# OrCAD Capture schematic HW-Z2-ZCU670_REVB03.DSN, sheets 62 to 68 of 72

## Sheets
62 062 RFMC 2.0 Connector 2: size Custom
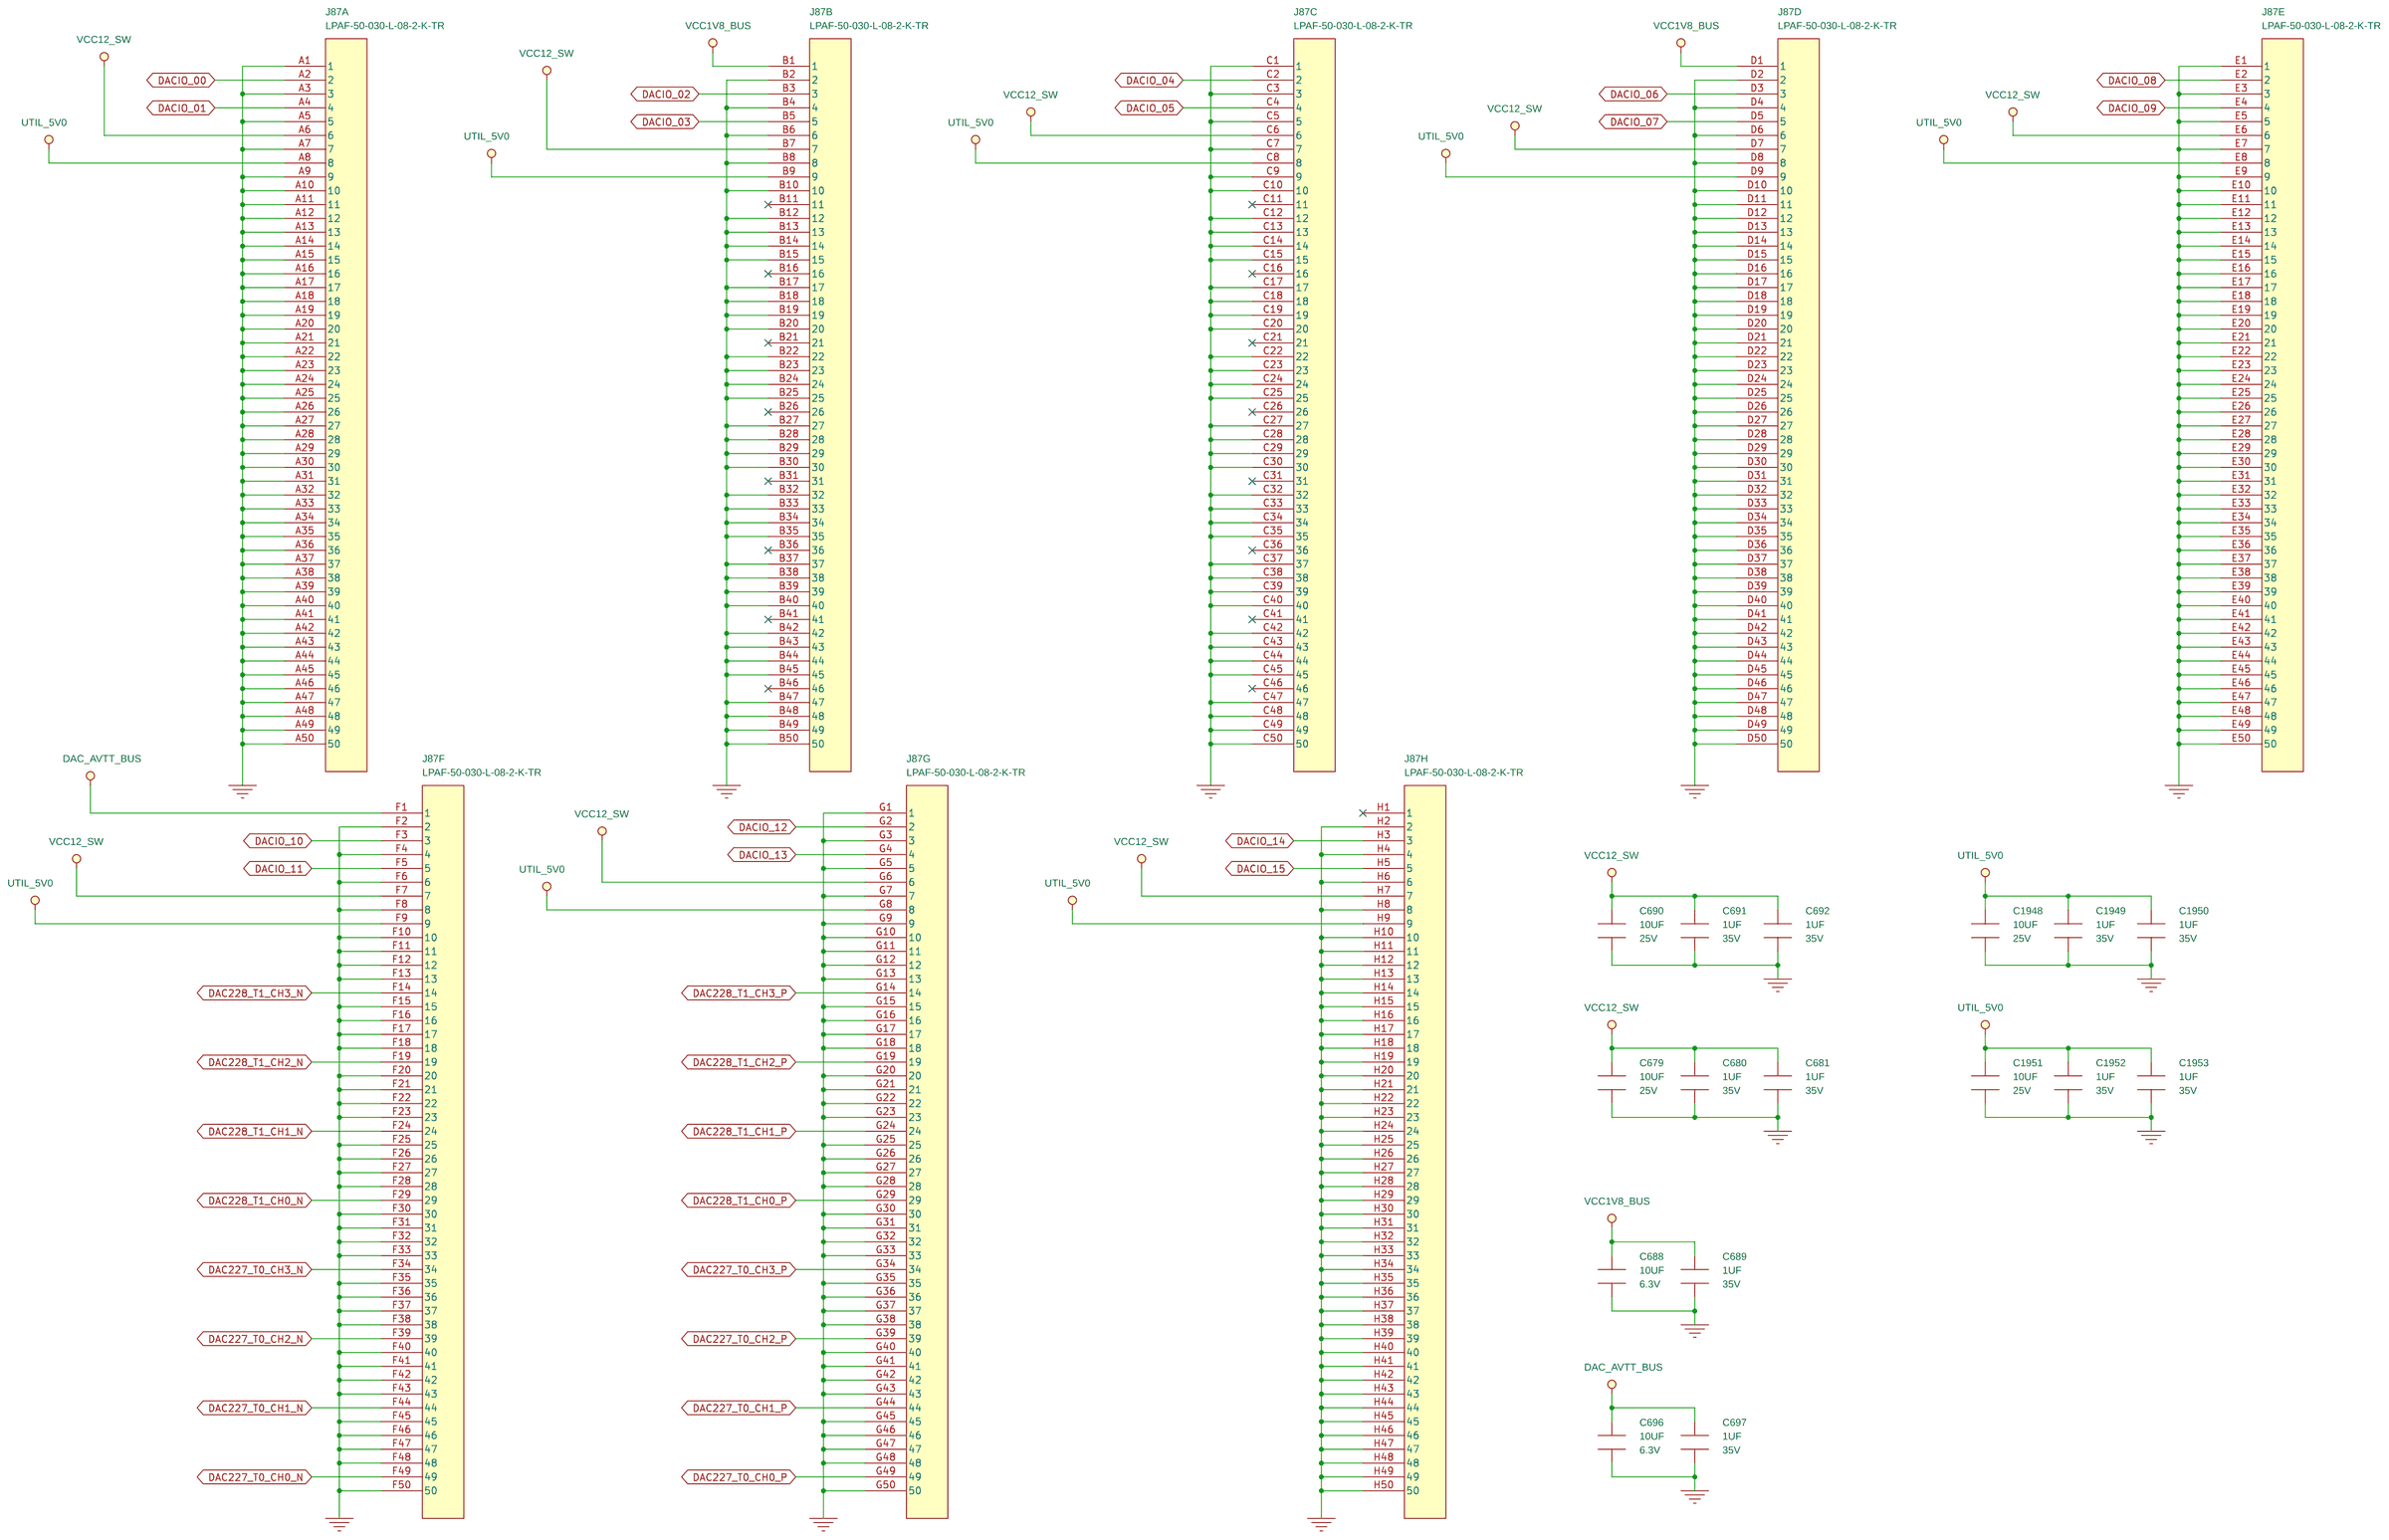
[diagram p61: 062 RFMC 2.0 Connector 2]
63 063 Mechanicals: size Custom
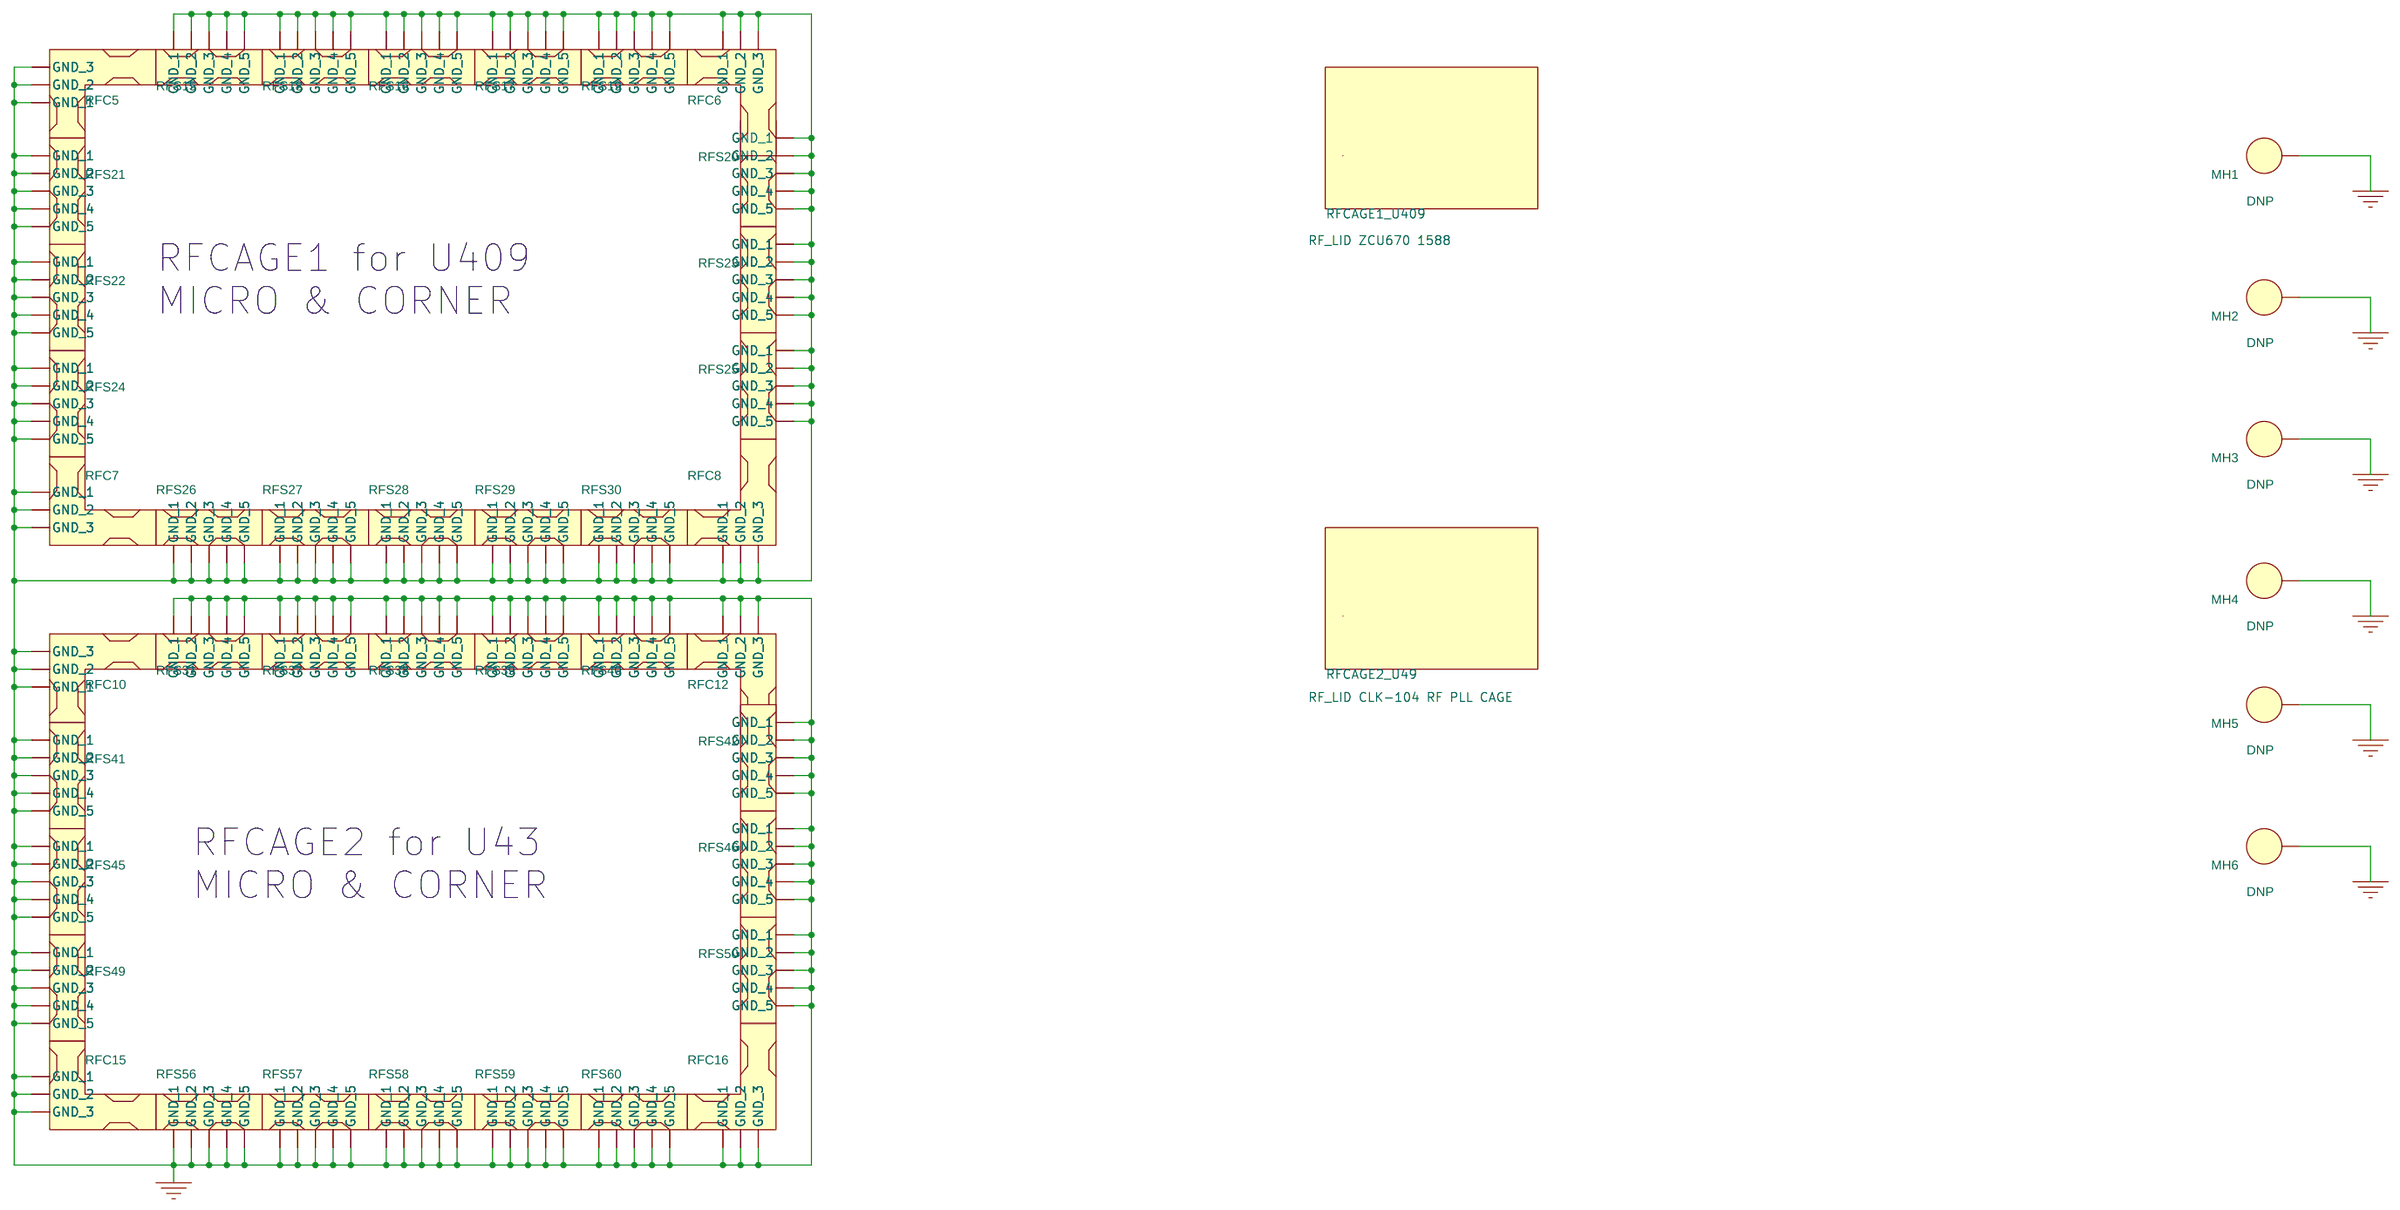
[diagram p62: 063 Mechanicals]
64 064 CLK104 Connector: size Custom
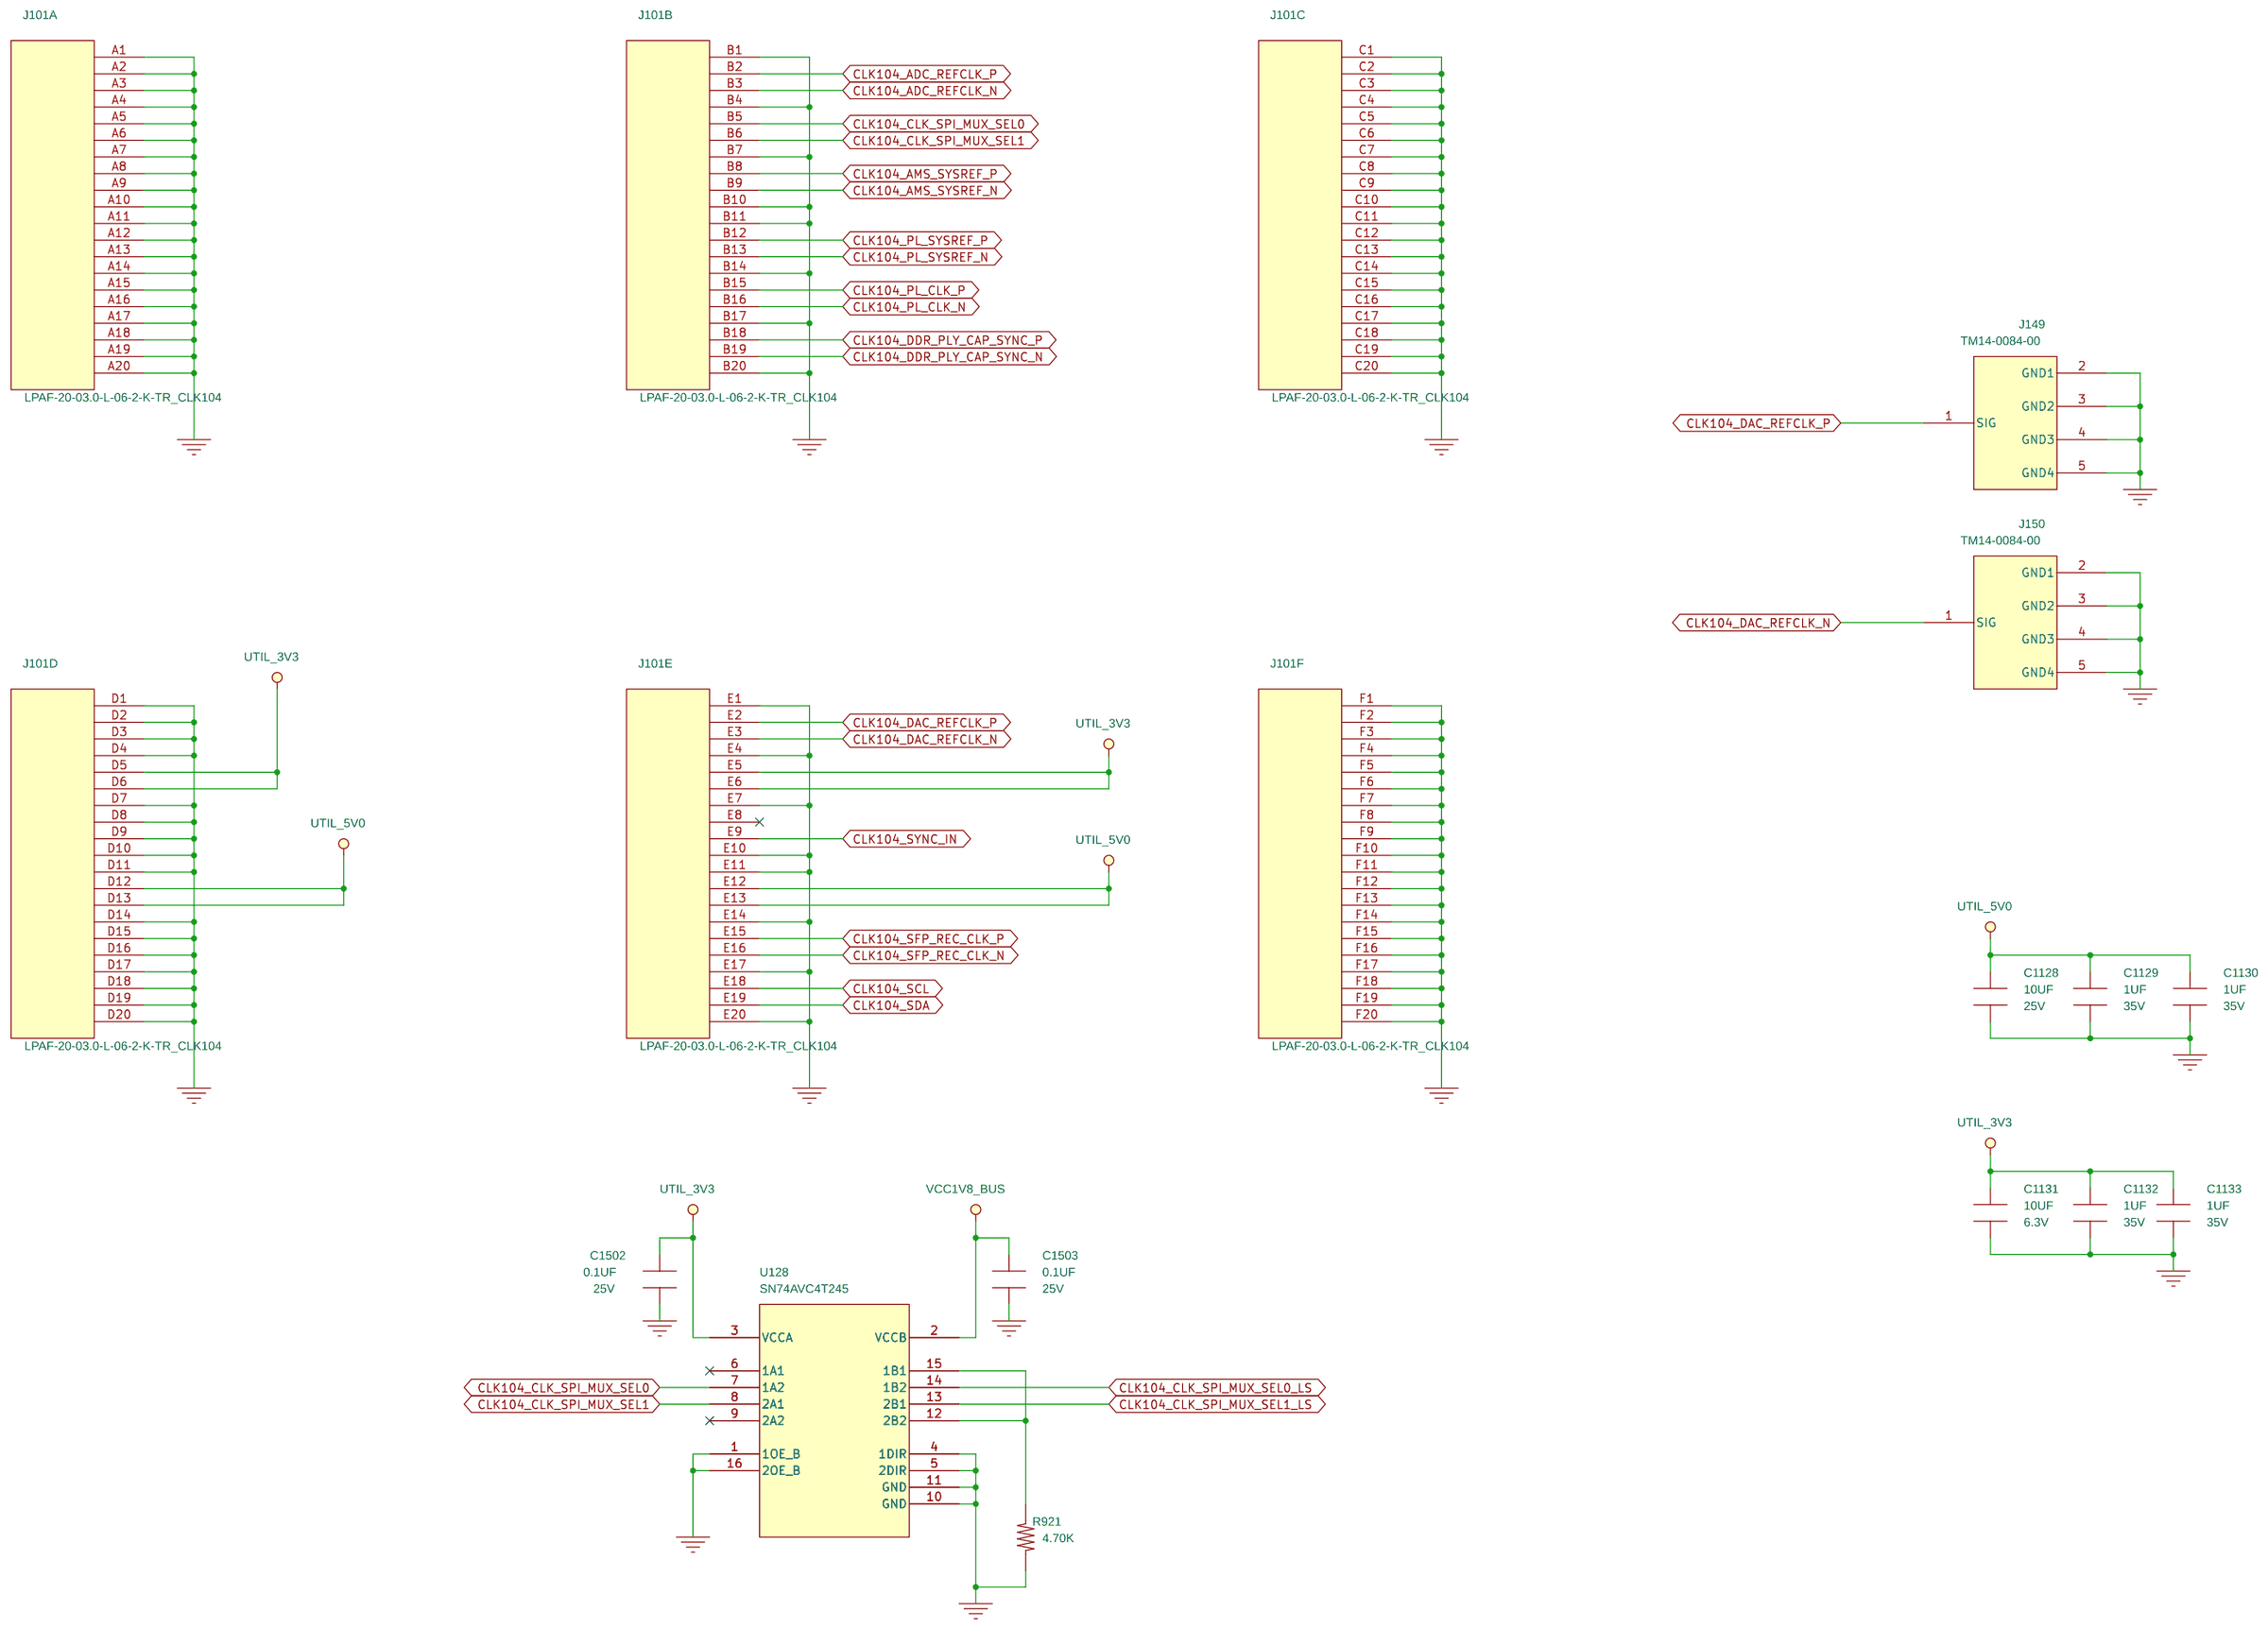
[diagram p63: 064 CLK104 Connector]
65 065 PL DDR4 C0 [7-0]: size Custom
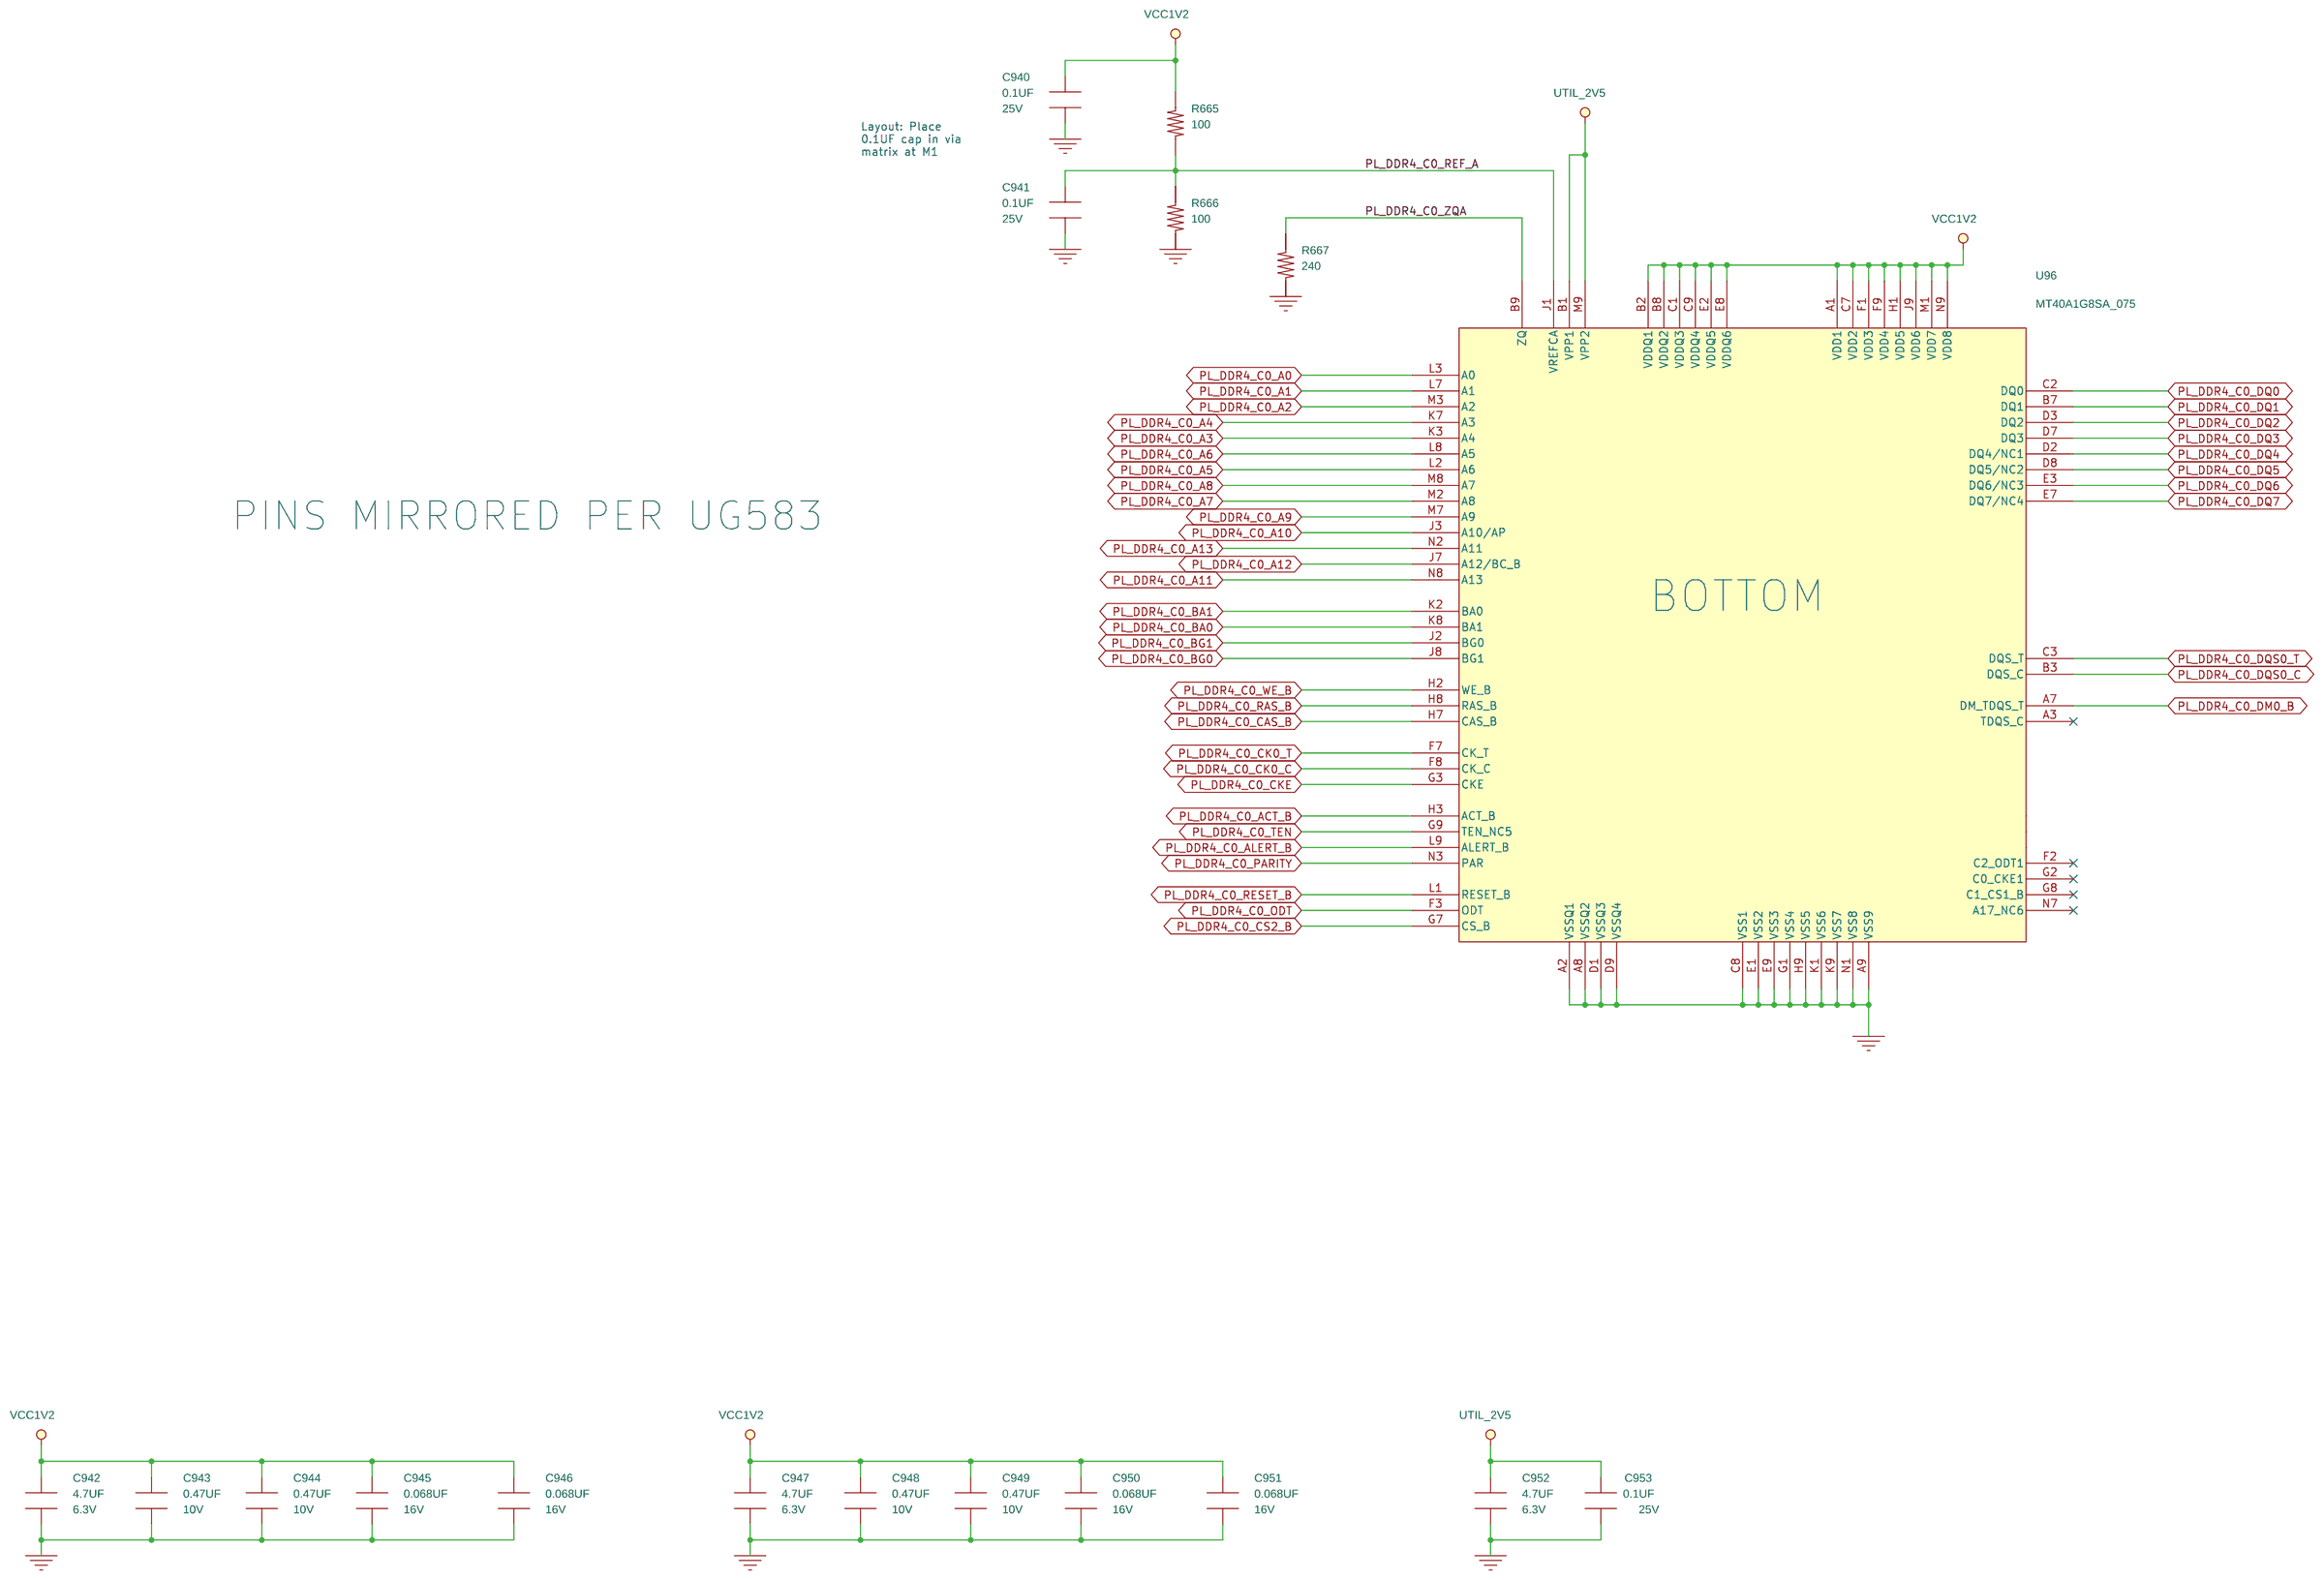
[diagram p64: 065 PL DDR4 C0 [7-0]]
66 066 PL DDR4 C0 [15-8]: size Custom
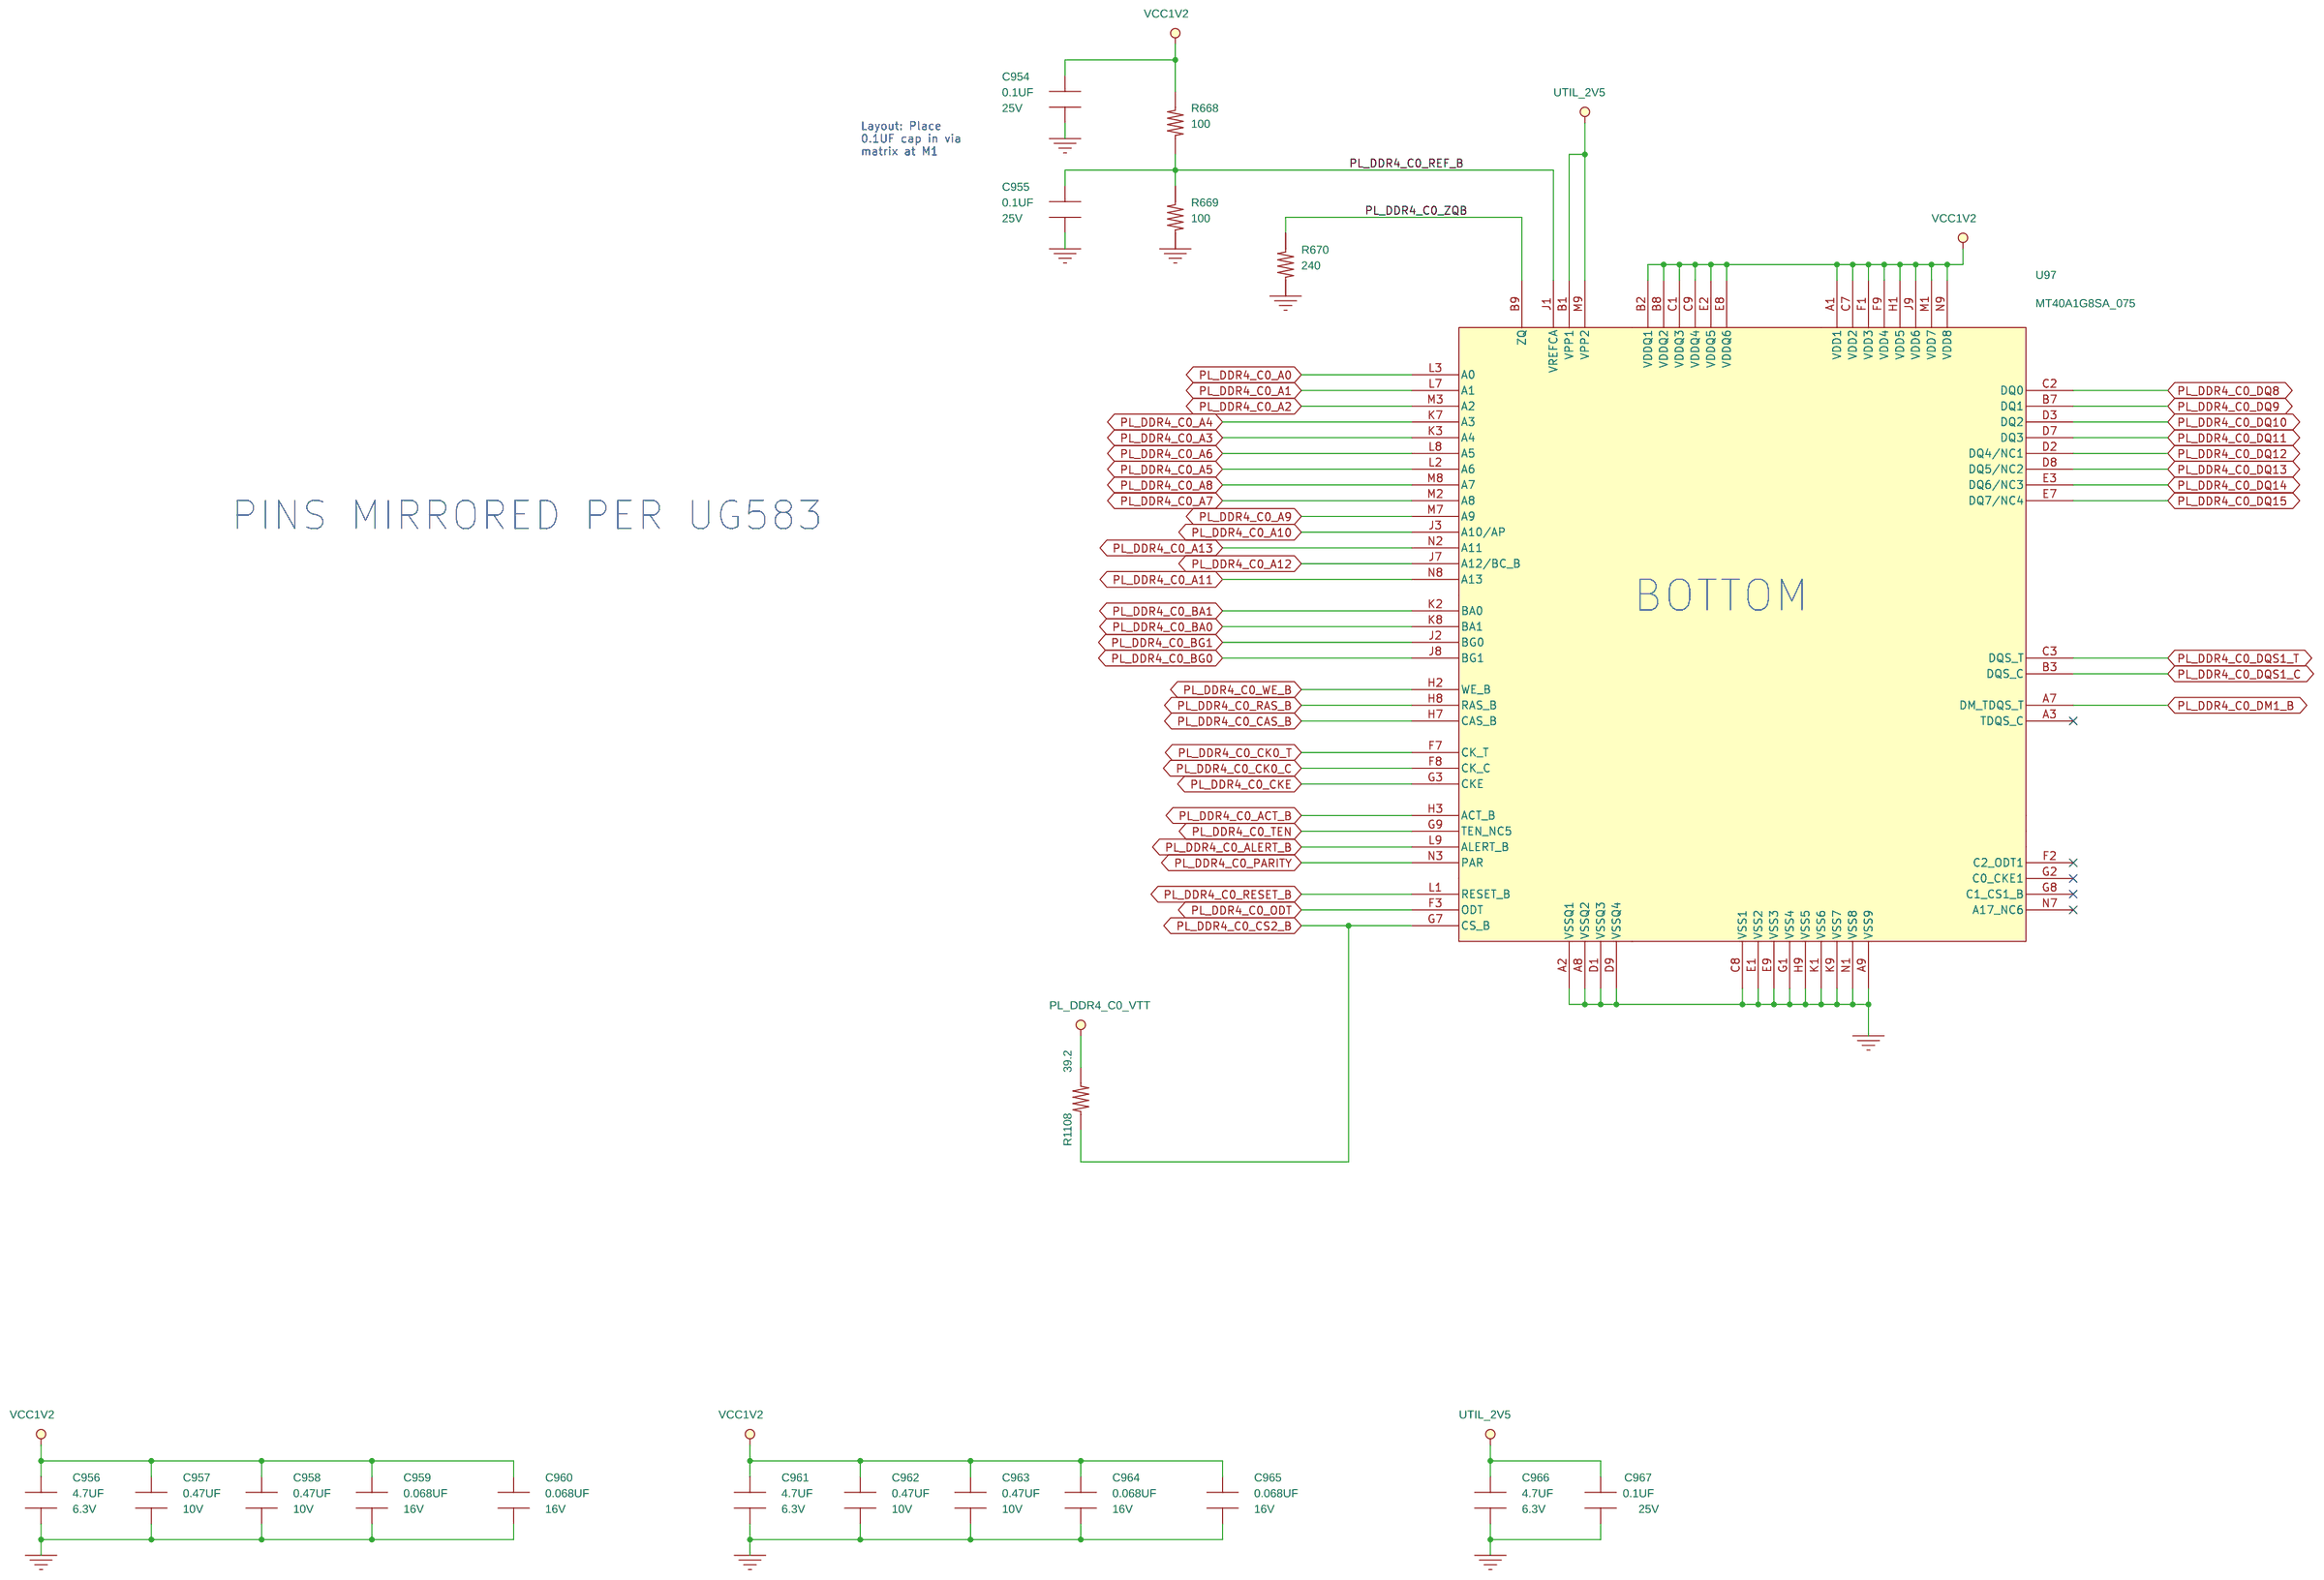
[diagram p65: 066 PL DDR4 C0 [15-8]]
67 067 PL DDR4 C0 [23-16]: size Custom
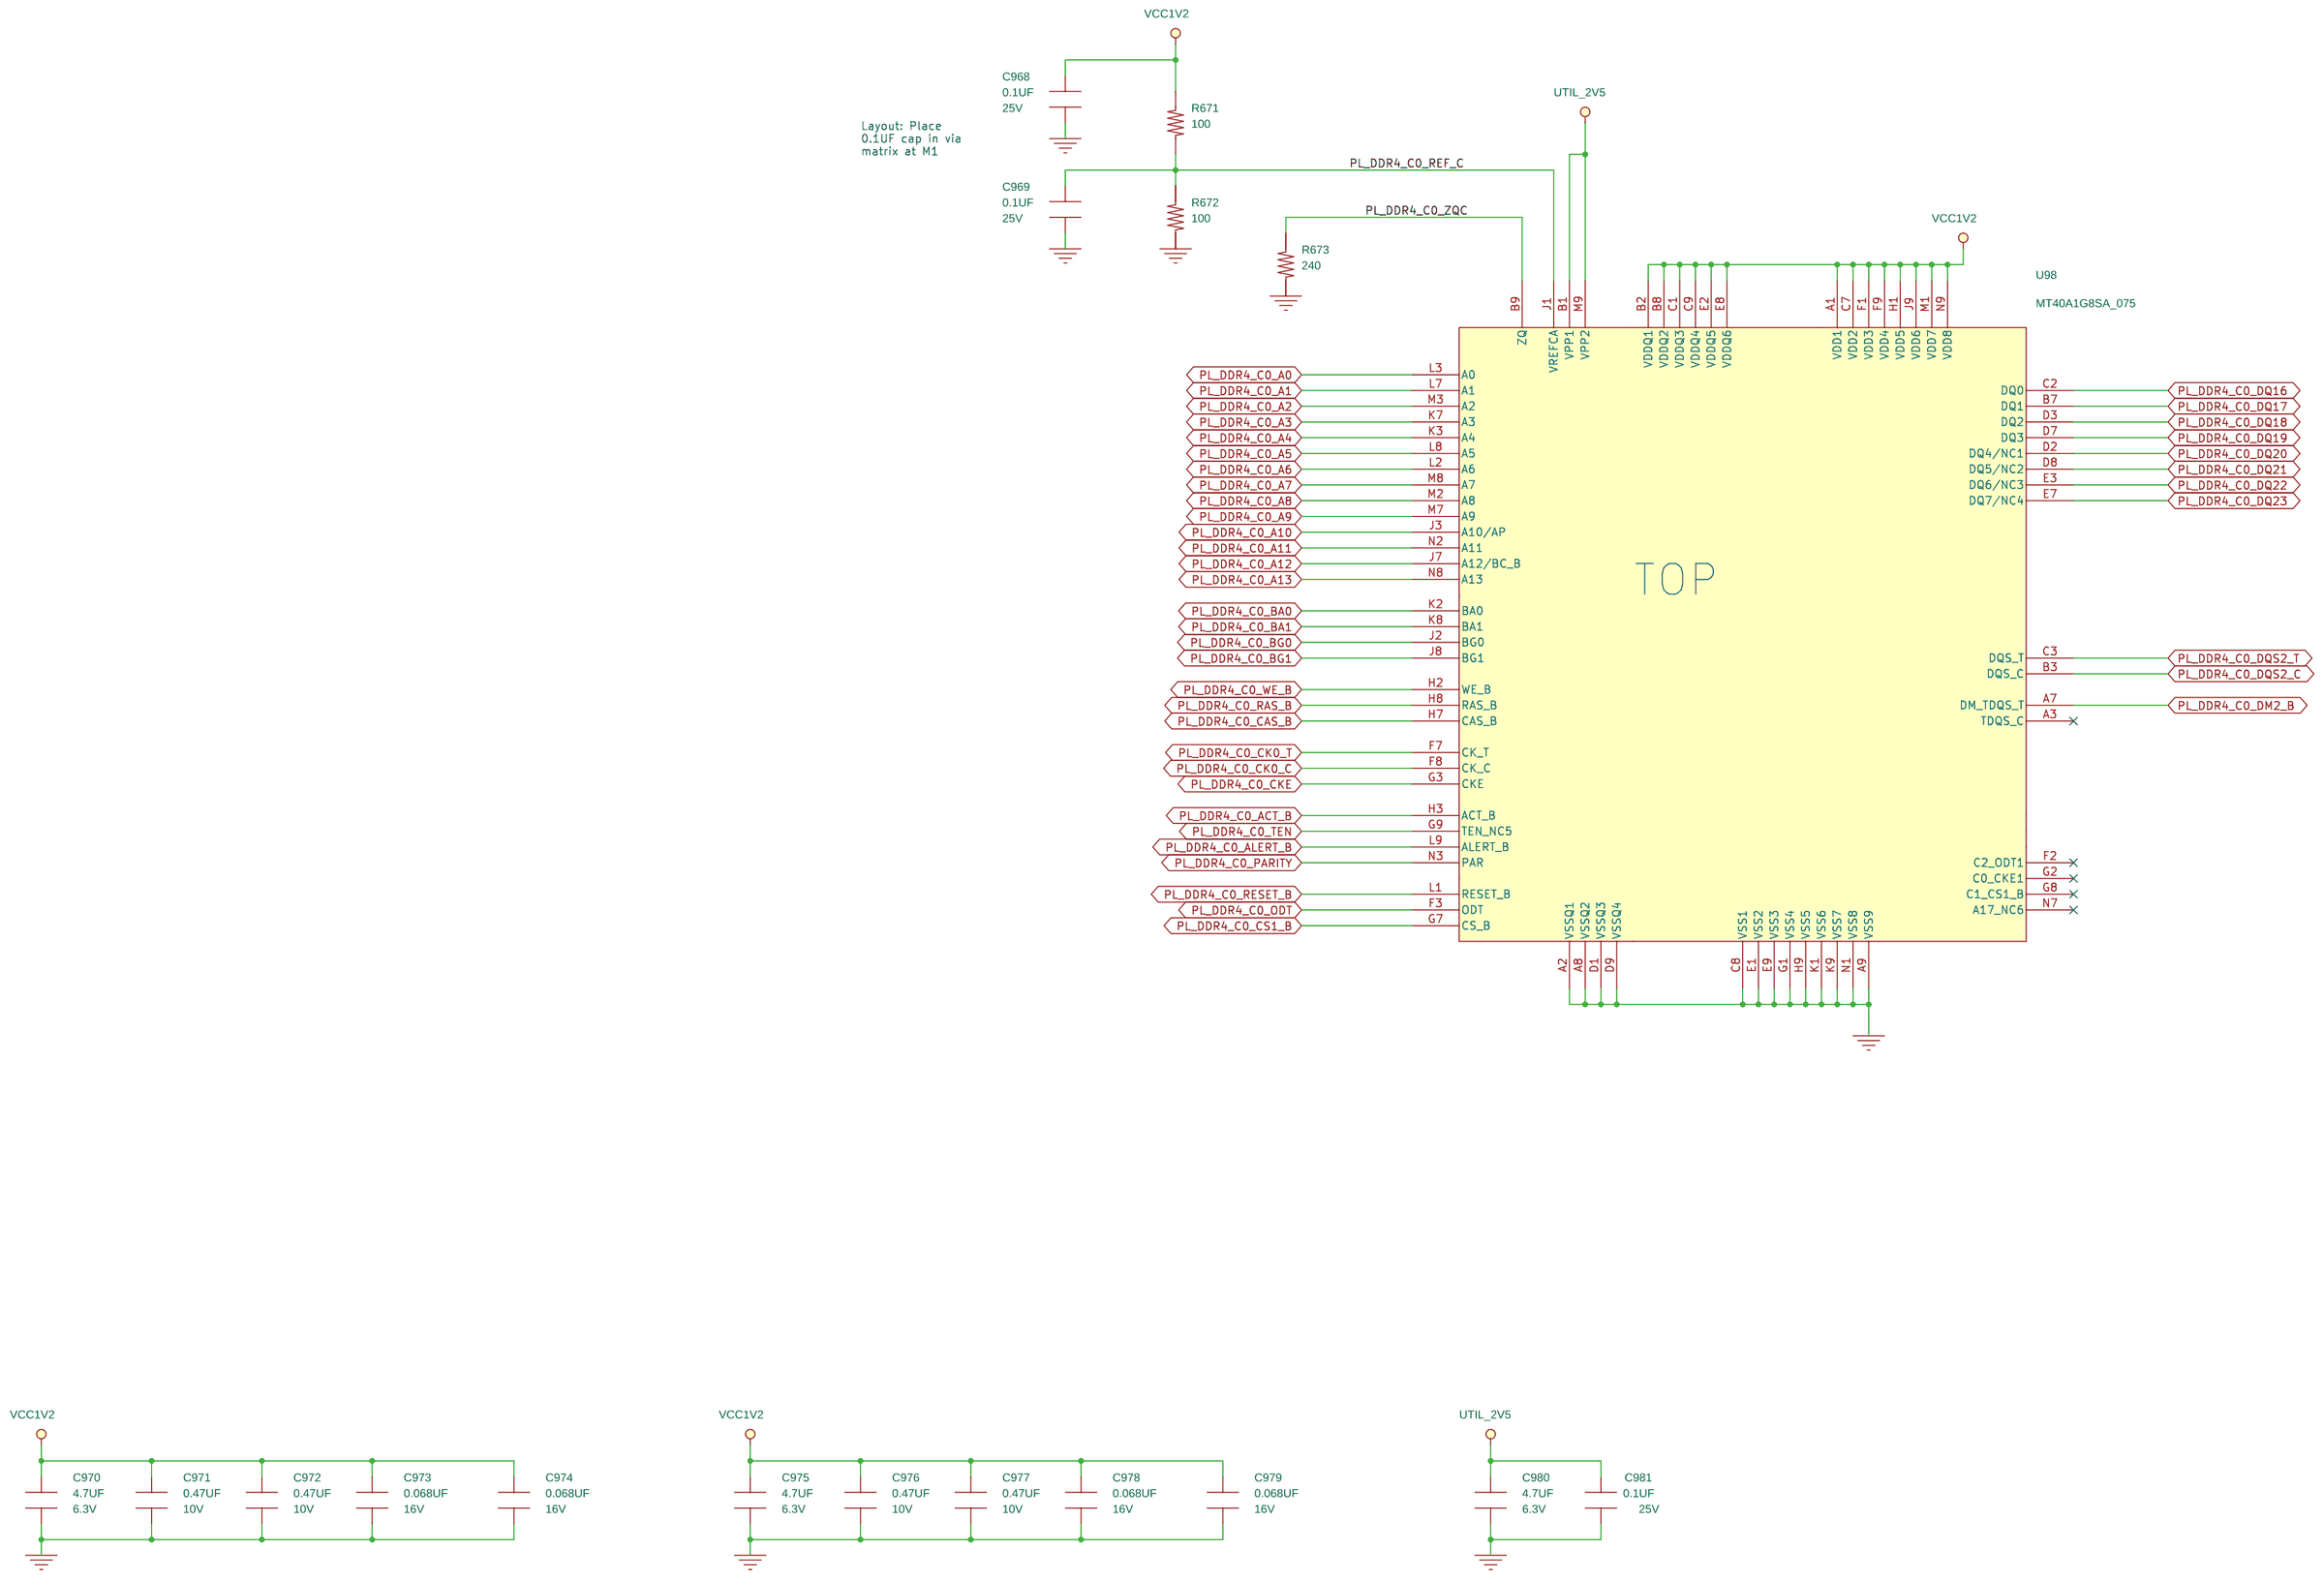
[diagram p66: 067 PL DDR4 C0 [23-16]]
68 068 PL DDR4 C0 [31-24]: size Custom
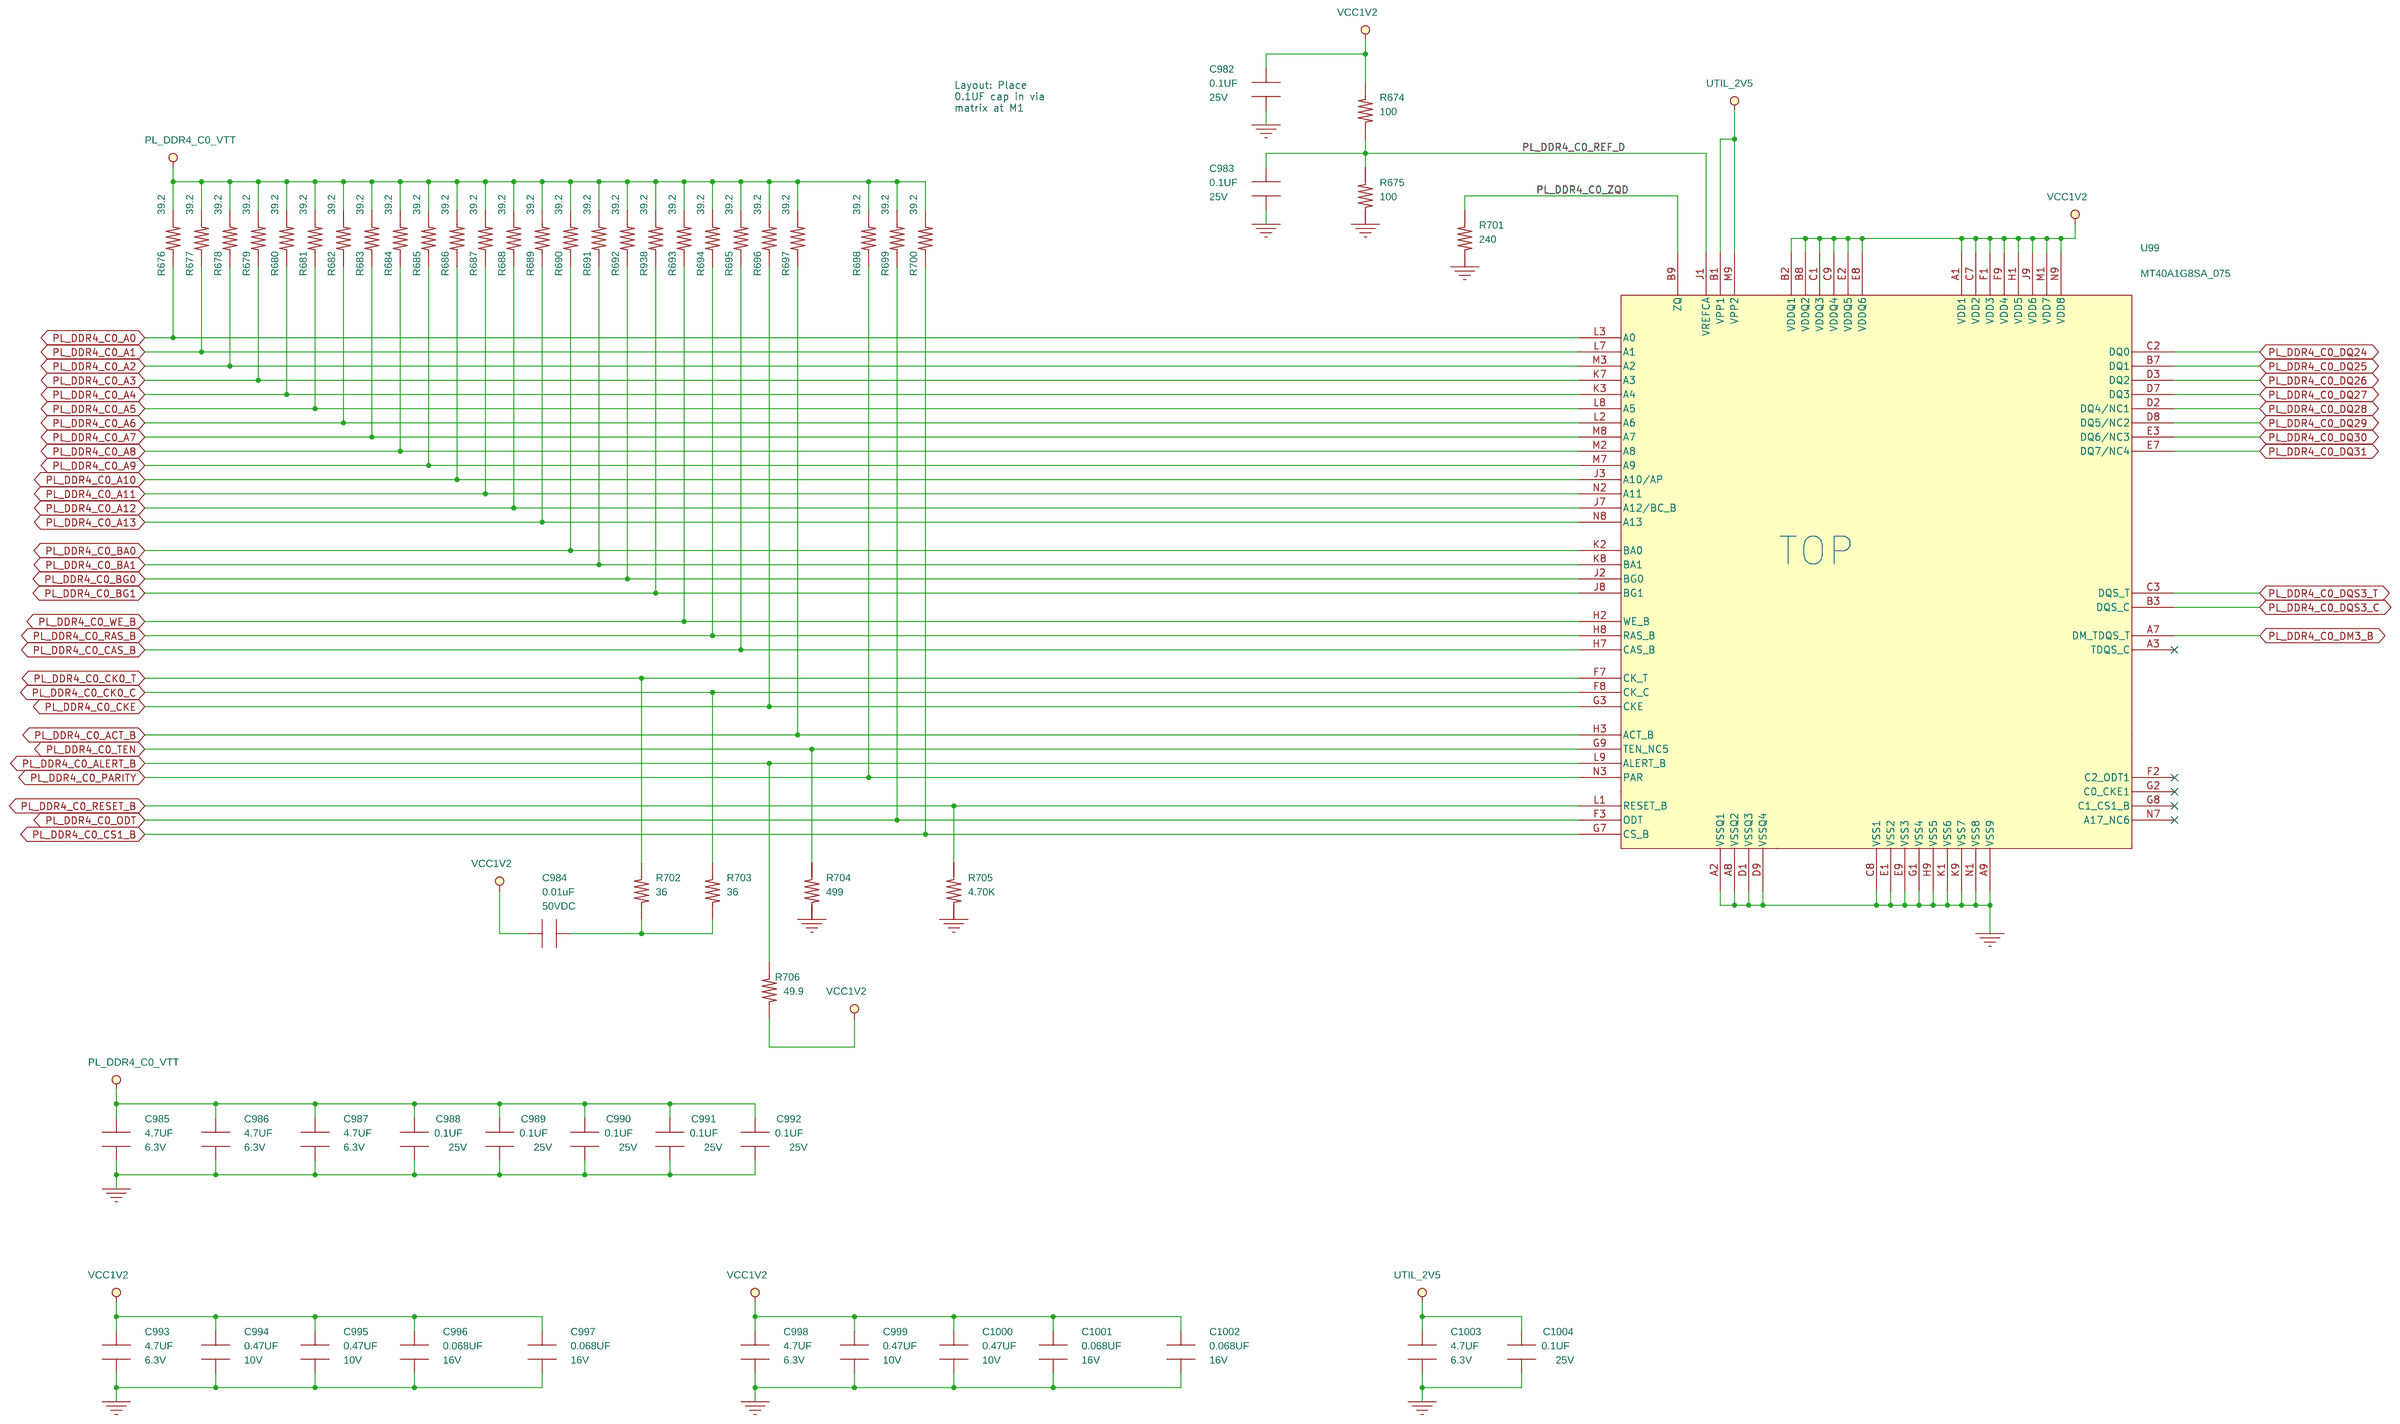
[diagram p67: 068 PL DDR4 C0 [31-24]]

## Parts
sheet 062 RFMC 2.0 Connector 2
C679  10UF  [CAPC320X250X220]
C680  1UF  [CAPC100X50X60]
C681  1UF  [CAPC100X50X60]
C688  10UF  [CAPC100X50X70]
C689  1UF  [CAPC100X50X60]
C690  10UF  [CAPC320X250X220]
C691  1UF  [CAPC100X50X60]
C692  1UF  [CAPC100X50X60]
C696  10UF  [CAPC100X50X70]
C697  1UF  [CAPC100X50X60]
C1948  10UF  [CAPC320X250X220]
C1949  1UF  [CAPC100X50X60]
C1950  1UF  [CAPC100X50X60]
C1951  10UF  [CAPC320X250X220]
C1952  1UF  [CAPC100X50X60]
C1953  1UF  [CAPC100X50X60]
J87  LPAF-50-030-L-08-2-K-TR  [SAMTEC_LPAF_50_030_L_08_2_K_TR]  (sections A,B,C,D,E,F,G,H)
sheet 063 Mechanicals
MH1  MH_156_300  [MH_300H156]
MH2  MH_156_300  [MH_300H156]
MH3  MH_156_300  [MH_300H156]
MH4  MH_156_300  [MH_300H156]
MH5  MH_156_300  [MH_300H156]
MH6  MH_156_300  [MH_300H156]
RFC5  S0981-46R  [RFI_SHLD_S0981_46R]
RFC6  S0981-46R  [RFI_SHLD_S0981_46R]
RFC7  S0981-46R  [RFI_SHLD_S0981_46R]
RFC8  S0981-46R  [RFI_SHLD_S0981_46R]
RFC10  S0981-46R  [RFI_SHLD_S0981_46R]
RFC12  S0981-46R  [RFI_SHLD_S0981_46R]
RFC15  S0981-46R  [RFI_SHLD_S0981_46R]
RFC16  S0981-46R  [RFI_SHLD_S0981_46R]
RFCAGE1_U409  RF_LID ZCU670 1588
RFCAGE2_U49  RF_LID CLK-104 RF PLL CAGE
RFS15  S0951-46R  [RFI_SHLD_S0951_46R]
RFS16  S0951-46R  [RFI_SHLD_S0951_46R]
RFS17  S0951-46R  [RFI_SHLD_S0951_46R]
RFS18  S0951-46R  [RFI_SHLD_S0951_46R]
RFS19  S0951-46R  [RFI_SHLD_S0951_46R]
RFS20  S0951-46R  [RFI_SHLD_S0951_46R]
RFS21  S0951-46R  [RFI_SHLD_S0951_46R]
RFS22  S0951-46R  [RFI_SHLD_S0951_46R]
RFS23  S0951-46R  [RFI_SHLD_S0951_46R]
RFS24  S0951-46R  [RFI_SHLD_S0951_46R]
RFS25  S0951-46R  [RFI_SHLD_S0951_46R]
RFS26  S0951-46R  [RFI_SHLD_S0951_46R]
RFS27  S0951-46R  [RFI_SHLD_S0951_46R]
RFS28  S0951-46R  [RFI_SHLD_S0951_46R]
RFS29  S0951-46R  [RFI_SHLD_S0951_46R]
RFS30  S0951-46R  [RFI_SHLD_S0951_46R]
RFS31  S0951-46R  [RFI_SHLD_S0951_46R]
RFS37  S0951-46R  [RFI_SHLD_S0951_46R]
RFS38  S0951-46R  [RFI_SHLD_S0951_46R]
RFS39  S0951-46R  [RFI_SHLD_S0951_46R]
RFS40  S0951-46R  [RFI_SHLD_S0951_46R]
RFS41  S0951-46R  [RFI_SHLD_S0951_46R]
RFS42  S0951-46R  [RFI_SHLD_S0951_46R]
RFS45  S0951-46R  [RFI_SHLD_S0951_46R]
RFS46  S0951-46R  [RFI_SHLD_S0951_46R]
RFS49  S0951-46R  [RFI_SHLD_S0951_46R]
RFS50  S0951-46R  [RFI_SHLD_S0951_46R]
RFS56  S0951-46R  [RFI_SHLD_S0951_46R]
RFS57  S0951-46R  [RFI_SHLD_S0951_46R]
RFS58  S0951-46R  [RFI_SHLD_S0951_46R]
RFS59  S0951-46R  [RFI_SHLD_S0951_46R]
RFS60  S0951-46R  [RFI_SHLD_S0951_46R]
sheet 064 CLK104 Connector
C1128  10UF  [CAPC320X250X220]
C1129  1UF  [CAPC100X50X60]
C1130  1UF  [CAPC100X50X60]
C1131  10UF  [CAPC100X50X70]
C1132  1UF  [CAPC100X50X60]
C1133  1UF  [CAPC100X50X60]
C1502  0.1UF  [CAPC100X50X55]
C1503  0.1UF  [CAPC100X50X55]
J101  LPAF-20-03.0-L-06-2-K-TR_CLK104  [SAMTEC_LPAF_20_03_XX_06_CLK104]  (sections A,B,C,D,E,F)
J149  TM14-0084-00  [CONN_CARLISE_TM14_0084_00]
J150  TM14-0084-00  [CONN_CARLISE_TM14_0084_00]
R921  4.70K  [RESC100X50X40]
U128  SN74AVC4T245  [QFN_RSV_16]
sheet 065 PL DDR4 C0 [7-0]
C940  0.1UF  [CAPC100X50X55]
C941  0.1UF  [CAPC100X50X55]
C942  4.7UF  [CAPC100X50X60]
C943  0.47UF  [CAPC100X50X55]
C944  0.47UF  [CAPC100X50X55]
C945  0.068UF  [CAPC100X50X55]
C946  0.068UF  [CAPC100X50X55]
C947  4.7UF  [CAPC100X50X60]
C948  0.47UF  [CAPC100X50X55]
C949  0.47UF  [CAPC100X50X55]
C950  0.068UF  [CAPC100X50X55]
C951  0.068UF  [CAPC100X50X55]
C952  4.7UF  [CAPC100X50X60]
C953  0.1UF  [CAPC100X50X55]
R665  100  [RESC60X30X30]
R666  100  [RESC60X30X30]
R667  240  [RESC100X50X40]
U96  MT40A1G8SA_075  [FBGA_DDR4_78P]
sheet 066 PL DDR4 C0 [15-8]
C954  0.1UF  [CAPC100X50X55]
C955  0.1UF  [CAPC100X50X55]
C956  4.7UF  [CAPC100X50X60]
C957  0.47UF  [CAPC100X50X55]
C958  0.47UF  [CAPC100X50X55]
C959  0.068UF  [CAPC100X50X55]
C960  0.068UF  [CAPC100X50X55]
C961  4.7UF  [CAPC100X50X60]
C962  0.47UF  [CAPC100X50X55]
C963  0.47UF  [CAPC100X50X55]
C964  0.068UF  [CAPC100X50X55]
C965  0.068UF  [CAPC100X50X55]
C966  4.7UF  [CAPC100X50X60]
C967  0.1UF  [CAPC100X50X55]
R668  100  [RESC60X30X30]
R669  100  [RESC60X30X30]
R670  240  [RESC100X50X40]
R1108  39.2  [RESC100X50X40]
U97  MT40A1G8SA_075  [FBGA_DDR4_78P]
sheet 067 PL DDR4 C0 [23-16]
C968  0.1UF  [CAPC100X50X55]
C969  0.1UF  [CAPC100X50X55]
C970  4.7UF  [CAPC100X50X60]
C971  0.47UF  [CAPC100X50X55]
C972  0.47UF  [CAPC100X50X55]
C973  0.068UF  [CAPC100X50X55]
C974  0.068UF  [CAPC100X50X55]
C975  4.7UF  [CAPC100X50X60]
C976  0.47UF  [CAPC100X50X55]
C977  0.47UF  [CAPC100X50X55]
C978  0.068UF  [CAPC100X50X55]
C979  0.068UF  [CAPC100X50X55]
C980  4.7UF  [CAPC100X50X60]
C981  0.1UF  [CAPC100X50X55]
R671  100  [RESC60X30X30]
R672  100  [RESC60X30X30]
R673  240  [RESC100X50X40]
U98  MT40A1G8SA_075  [FBGA_DDR4_78P]
sheet 068 PL DDR4 C0 [31-24]
C982  0.1UF  [CAPC100X50X55]
C983  0.1UF  [CAPC100X50X55]
C984  0.01uF  [CAPC100X50X55]
C985  4.7UF  [CAPC100X50X60]
C986  4.7UF  [CAPC100X50X60]
C987  4.7UF  [CAPC100X50X60]
C988  0.1UF  [CAPC100X50X55]
C989  0.1UF  [CAPC100X50X55]
C990  0.1UF  [CAPC100X50X55]
C991  0.1UF  [CAPC100X50X55]
C992  0.1UF  [CAPC100X50X55]
C993  4.7UF  [CAPC100X50X60]
C994  0.47UF  [CAPC100X50X55]
C995  0.47UF  [CAPC100X50X55]
C996  0.068UF  [CAPC100X50X55]
C997  0.068UF  [CAPC100X50X55]
C998  4.7UF  [CAPC100X50X60]
C999  0.47UF  [CAPC100X50X55]
C1000  0.47UF  [CAPC100X50X55]
C1001  0.068UF  [CAPC100X50X55]
C1002  0.068UF  [CAPC100X50X55]
C1003  4.7UF  [CAPC100X50X60]
C1004  0.1UF  [CAPC100X50X55]
R674  100  [RESC60X30X30]
R675  100  [RESC60X30X30]
R676  39.2  [RESC100X50X40]
R677  39.2  [RESC100X50X40]
R678  39.2  [RESC100X50X40]
R679  39.2  [RESC100X50X40]
R680  39.2  [RESC100X50X40]
R681  39.2  [RESC100X50X40]
R682  39.2  [RESC100X50X40]
R683  39.2  [RESC100X50X40]
R684  39.2  [RESC100X50X40]
R685  39.2  [RESC100X50X40]
R686  39.2  [RESC100X50X40]
R687  39.2  [RESC100X50X40]
R688  39.2  [RESC100X50X40]
R689  39.2  [RESC100X50X40]
R690  39.2  [RESC100X50X40]
R691  39.2  [RESC100X50X40]
R692  39.2  [RESC100X50X40]
R693  39.2  [RESC100X50X40]
R694  39.2  [RESC100X50X40]
R695  39.2  [RESC100X50X40]
R696  39.2  [RESC100X50X40]
R697  39.2  [RESC100X50X40]
R698  39.2  [RESC100X50X40]
R699  39.2  [RESC100X50X40]
R700  39.2  [RESC100X50X40]
R701  240  [RESC100X50X40]
R702  36  [RESC100X50X40]
R703  36  [RESC100X50X40]
R704  499  [RESC100X50X40]
R705  4.70K  [RESC100X50X40]
R706  49.9  [RESC100X50X40]
R938  39.2  [RESC100X50X40]
U99  MT40A1G8SA_075  [FBGA_DDR4_78P]

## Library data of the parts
C679 C690 C1128 C1948 C1951 = CAP_NP: Cap Cer 10uF 10% 25V X5R 1210; ALT_SYMBOLS: CAPC320X250X220RND; Agile Part Number: CAP-00113-01; CIP Link: http://xsjbrdwin1/CIP-E/Component/Index/All?pn=100123; Dielectric: X5R; Dielectric Type: X5R; OWNER: 3709; PRICE: 0.18; Part Type: CERAMIC; PartType: CERAMIC; ROHS: Yes; Tolerance: 10%; Voltage: 25V; barcode: 100123
C680 C681 C689 C691 C692 C697 C1129 C1130 C1132 C1133 C1949 C1950 C1952 C1953 = CAP_NP: Cap Cer 1uF 10% 35V X5R 0402; ALT_SYMBOLS: CAPC100X50X60RND; Agile Part Number: CAP-00165-01; CIP Link: http://xsjbrdwin1/CIP-E/Component/Index/All?pn=100192; Dielectric: X5R; Dielectric Type: X5R; OWNER: 3709; PRICE: 0.04; Part Type: CERAMIC; PartType: CERAMIC; ROHS: Yes; Tolerance: 10%; Voltage: 35V; barcode: 100192
C688 C696 C1131 = CAP_NP: Cap Cer 10uF 20%  6.3V X6S 0402; ALT_SYMBOLS: CAPC100X50X55RND; Agile Part Number: CAP-00035-01; CIP Link: http://xsjbrdwin1/CIP-E/Component/Index/All?pn=100268; Dielectric: X5R; Dielectric Type: X6S; OWNER: 3670; PRICE: 0.04; Part Type: CERAMIC; PartType: CERAMIC; ROHS: Yes; Tolerance: 20%; Voltage: 6.3V; barcode: 100268
J87 = LPAF-50-030-L-08-2-K-TR: Conn Rcpt Female Vert 400 Pos 8x50 1.27mm P Black SMT; Agile Part Number: CON-00235-01; Barcode: 40000017; CIP Link: http://xsjbrdwin1/CIP-E/Component/Index/All?pn=40000017; Part Type: HEADER; Pitch: 0.8MM
MH1-MH6 = HOLE: MOUNTING HOLE, 156 HOLE 300 PAD; ASSEMBLY_OPTIONS: DNP; Barcode: 96000008; CIP Link: http://xsjbrdwin1/CIP-E/Component/Index/All?pn=96000008; OWNER: 6176; Part Type: Unassigned Part Type; PartType: PCB LAYOUT; ROHS: 0
RFC5-RFC8 RFC10 RFC12 RFC15 RFC16 = S0981-46R: RFI SHIELD CLIP R/A TIN SMD; Barcode: 90000006; CIP Link: http://xsjbrdwin1/CIP-E/Component/Index/All?pn=90000006; Part Type: Mechanical Part
RFCAGE1_U409 = RF_LID: Shield EMI 33.14x23.75x5.72mm SMT; Barcode: 90000026; CIP Link: http://xsjbrdwin1/CIP-E/Component/Index/All?pn=90000026; Part Type: Mechanical Part
RFCAGE2_U49 = RF_LID: EMI LID, CLK-104 RF PLL CAGE; Barcode: 90000008; CIP Link: http://xsjbrdwin1/CIP-E/Component/Index/All?pn=90000008; Part Type: Mechanical Part
RFS15-RFS31 RFS37-RFS42 RFS45 RFS46 RFS49 RFS50 RFS56-RFS60 = S0951-46R: RFI SHIELD CLIP MINI TIN SMD; Barcode: 90000005; CIP Link: http://xsjbrdwin1/CIP-E/Component/Index/All?pn=90000005; Part Type: Mechanical Part
C1502 C1503 = CAP_NP: Cap Cer 100nF 10% 25V X5R 0402; ALT_SYMBOLS: CAPC100X50X55RND; Agile Part Number: CAP-00068-01; CIP Link: http://xsjbrdwin1/CIP-E/Component/Index/All?pn=100040; Dielectric Type: X5R; OWNER: 4001; PRICE: 0.01; Part Type: CERAMIC; PartType: CERAMIC; ROHS: Yes; Tolerance: 10%; Voltage: 25V; barcode: 100040
J101 = LPAF-20-xx.x-x-06-x-x-xx: Conn Rcpt Female Vert 120 Pos 6x20 1.27mm P Black SMT; Agile Part Number: CON-00298-01; Barcode: 40000040; CIP Link: http://xsjbrdwin1/CIP-E/Component/Index/All?pn=40000040; Number of Pins: 120; Part Type: CONNECTOR; Pitch: 0.050" (1.27mm)
J149 J150 = SMA-5PIN: Conn Rcpt SSMP Male Vert 50R 50GHz SMT/TH Non-Detent; Agile Part Number: CON-00301-01; Barcode: 40000016; CIP Link: http://xsjbrdwin1/CIP-E/Component/Index/All?pn=40000016; Number of Pins: 5; Part Type: --\--
R921 = RES: Res 4K7 1% 1/16W 100PPM 50V 0402; ALT_SYMBOLS: RESC100X50X40RND; Agile Part Number: RES-00035-01; Barcode: 200067; CIP Link: http://xsjbrdwin1/CIP-E/Component/Index/All?pn=200067; OWNER: 3670; PRICE: 0.01; Part Type: SMT - 1%; PartType: SMT - 1%; Power: 1/16W; ROHS: Yes; Rated Power: 1/16W; Tolerance: 1%; primarykey: 128
U128 = SN74AVC4T245: IC Lvl Trans 4-Bit Bidir 380Mbps 1.2-3.6V 50mA UQFN-16; Agile Part Number: ICS-00049-01; Barcode: 500013; CIP Link: http://xsjbrdwin1/CIP-E/Component/Index/All?pn=500013; Family: BUS TRANSCEIVER; Part Type: BUS TRANSCEIVER; ROHS: Yes
C940 C941 C953-C955 C967-C969 C981-C983 C988-C992 C1004 = CAP_NP: Cap Cer 100nF 10% 25V X5R 0402; ALT_SYMBOLS: CAPC100X50X55RND; Agile Part Number: CAP-00068-01; CIP Link: http://xsjbrdwin1/CIP-E/Component/Index/All?pn=100040; Dielectric: X5R; Dielectric Type: X5R; OWNER: 4001; PRICE: 0.01; Part Type: CERAMIC; PartType: CERAMIC; ROHS: Yes; Tolerance: 10%; Voltage: 25V; barcode: 100040
C942 C947 C952 C956 C961 C966 C970 C975 C980 C985-C987 C993 C998 C1003 = CAP_NP: Cap Cer 4.7uF 20% 6.3V X5R 0402; ALT_SYMBOLS: CAPC100X50X60RND; Agile Part Number: CAP-00085-01; CIP Link: http://xsjbrdwin1/CIP-E/Component/Index/All?pn=100067; Dielectric: X5R; Dielectric Type: X5R; OWNER: 3709; PRICE: 0.06; Part Type: CERAMIC; PartType: CERAMIC; ROHS: Yes; Tolerance: 20%; Voltage: 6.3V; barcode: 100067
C943 C944 C948 C949 C957 C958 C962 C963 C971 C972 C976 C977 C994 C995 C999 C1000 = CAP_NP: Cap Cer 470nF 10% 10V X5R 0402; ALT_SYMBOLS: CAPC100X50X55RND; Agile Part Number: CAP-00054-01; CIP Link: http://xsjbrdwin1/CIP-E/Component/Index/All?pn=100022; Dielectric: X5R; Dielectric Type: X5R; OWNER: 4001; PRICE: 0.02; Part Type: CERAMIC; PartType: CERAMIC; ROHS: Yes; Tolerance: 10%; Voltage: 10V; barcode: 100022
C945 C946 C950 C951 C959 C960 C964 C965 C973 C974 C978 C979 C996 C997 C1001 C1002 = CAP_NP: Cap Cer 68nF 10% 16V X7R 0402; ALT_SYMBOLS: CAPC100X50X55RND; Agile Part Number: CAP-00018-01; CIP Link: http://xsjbrdwin1/CIP-E/Component/Index/All?pn=100125; Dielectric: X7R; Dielectric Type: X7R; OWNER: 3709; PRICE: 0; Part Type: CERAMIC; PartType: CERAMIC; ROHS: Yes; Tolerance: 10%; Voltage: 16V; barcode: 100125
R665 R666 R668 R669 R671 R672 R674 R675 = RES: Res 100R 5% 1/20W 200PPM 25V 0201; Agile Part Number: RES-00026-01; Barcode: 200126; CIP Link: http://xsjbrdwin1/CIP-E/Component/Index/All?pn=200126; OWNER: 3709; PRICE: 0; Part Type: SMT - 1%; PartType: SMT - 1%; Power: 1/20W; ROHS: Yes; Rated Power: 1/20W; Tolerance: 5%; primarykey: 85
R667 R670 R673 R701 = RES: Res 240R 1% 1/16W 100PPM 50V 0402; ALT_SYMBOLS: RESC100X50X40RND; Agile Part Number: RES-00018-01; Barcode: 200046; CIP Link: http://xsjbrdwin1/CIP-E/Component/Index/All?pn=200046; OWNER: 3670; PRICE: 0; Part Type: SMT - 1%; PartType: SMT - 1%; Power: 1/10W; ROHS: Yes; Rated Power: 1/16W; Tolerance: 1%; primarykey: 103
U96-U99 = MT40A1G8WE: IC SDRAM DDR4 8Gb 1Gx8 1.33GHz 1.2V 7.5x11mm FBGA-78; Agile Part Number: 1310642; Barcode: 50000107; CIP Link: http://xsjbrdwin1/CIP-E/Component/Index/All?pn=50000107; Part Type: MEMORY
R676-R700 R938 R1108 = RES: Res 39R2 1% 1/16W 100PPM 50V 0402; Agile Part Number: RES-00024-01; Barcode: 200329; CIP Link: http://xsjbrdwin1/CIP-E/Component/Index/All?pn=200329; OWNER: 3709; PRICE: 0; Part Type: SMT - 1%; PartType: SMT - 1%; Power: 1/10W; ROHS: Yes; Rated Power: 1/16W; Tolerance: 1%; primarykey: 342
C984 = CAP_NP: Cap Cer 10nF 10% 50V X7R 0402; ALT_SYMBOLS: CAPC100X50X55RND; Agile Part Number: CAP-00031-01; CIP Link: http://xsjbrdwin1/CIP-E/Component/Index/All?pn=100003; Dielectric: X5R; Dielectric Type: X7R; OWNER: 4001; PRICE: 0; Part Type: CERAMIC; PartType: CERAMIC; ROHS: Yes; Tolerance: 10%; Voltage: 50VDC; barcode: 100003
R702 R703 = RES: Res 36R 1% 1/16W 100PPM 50V 0402; Agile Part Number: RES-00014-01; Barcode: 200260; CIP Link: http://xsjbrdwin1/CIP-E/Component/Index/All?pn=200260; OWNER: 3709; PRICE: 0; Part Type: SMT - 1%; PartType: SMT - 1%; Power: 1/10W; ROHS: Yes; Rated Power: 1/16W; Tolerance: 1%; primarykey: 302
R704 = RES: Res 499R 1% 1/16W 100PPM 50V 0402; ALT_SYMBOLS: RESC100X50X40RND; Agile Part Number: RES-00028-01; Barcode: 200071; CIP Link: http://xsjbrdwin1/CIP-E/Component/Index/All?pn=200071; OWNER: 10460; PRICE: 0; Part Type: SMT - 1%; PartType: SMT - 1%; Power: 1/10W; ROHS: Yes; Rated Power: 1/16W; Tolerance: 1%; primarykey: 79
R705 = RES: Res 4K7 1% 1/16W 100PPM 50V 0402; ALT_SYMBOLS: RESC100X50X40RND; Agile Part Number: RES-00035-01; Barcode: 200067; CIP Link: http://xsjbrdwin1/CIP-E/Component/Index/All?pn=200067; OWNER: 4001; PRICE: 0; Part Type: SMT - 1%; PartType: SMT - 1%; Power: 1/16W; ROHS: Yes; Rated Power: 1/16W; Tolerance: 1%; primarykey: 7
R706 = RES: Res 49R9 1% 1/16W 100PPM 50V 0402; ALT_SYMBOLS: RESC100X50X40RND; Agile Part Number: RES-00104-01; Barcode: 200073; CIP Link: http://xsjbrdwin1/CIP-E/Component/Index/All?pn=200073; OWNER: 3670; PRICE: 0.01; Part Type: SMT - 1%; PartType: SMT - 1%; Power: 1/16W; ROHS: Yes; Rated Power: 1/16W; Tolerance: 1%; primarykey: 128

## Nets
GND: C679.2 C680.2 C681.2 C688.2 C689.2 C690.2 C691.2 C692.2 C696.2 C697.2 C940.2 C941.2 C942.2 C943.2 C944.2 C945.2 C946.2 C947.2 C948.2 C949.2 C950.2 C951.2 C952.2 C953.2 C954.2 C955.2 C956.2 C957.2 C958.2 C959.2 C960.2 C961.2 C962.2 C963.2 C964.2 C965.2 C966.2 C967.2 C968.2 C969.2 C970.2 C971.2 C972.2 C973.2 C974.2 C975.2 C976.2 C977.2 C978.2 C979.2 C980.2 C981.2 C982.2 C983.2 C985.2 C986.2 C987.2 C988.2 C989.2 C990.2 C991.2 C992.2 C993.2 C994.2 C995.2 C996.2 C997.2 C998.2 C999.2 C1000.2 C1001.2 C1002.2 C1003.2 C1004.2 C1128.2 C1129.2 C1130.2 C1131.2 C1132.2 C1133.2 C1502.2 C1503.2 C1948.2 C1949.2 C1950.2 C1951.2 C1952.2 C1953.2 J87.A1(1) J87.A3(3) J87.A5(5) J87.A7(7) J87.A9(9) J87.A10(10) J87.A11(11) J87.A12(12) J87.A13(13) J87.A14(14) J87.A15(15) J87.A16(16) J87.A17(17) J87.A18(18) J87.A19(19) J87.A20(20) J87.A21(21) J87.A22(22) J87.A23(23) J87.A24(24) J87.A25(25) J87.A26(26) J87.A27(27) J87.A28(28) J87.A29(29) J87.A30(30) J87.A31(31) J87.A32(32) J87.A33(33) J87.A34(34) J87.A35(35) J87.A36(36) J87.A37(37) J87.A38(38) J87.A39(39) J87.A40(40) J87.A41(41) J87.A42(42) J87.A43(43) J87.A44(44) J87.A45(45) J87.A46(46) J87.A47(47) J87.A48(48) J87.A49(49) J87.A50(50) J87.B2(2) J87.B4(4) J87.B6(6) J87.B8(8) J87.B10(10) J87.B12(12) J87.B13(13) J87.B14(14) J87.B15(15) J87.B17(17) J87.B18(18) J87.B19(19) J87.B20(20) J87.B22(22) J87.B23(23) J87.B24(24) J87.B25(25) J87.B27(27) J87.B28(28) J87.B29(29) J87.B30(30) J87.B32(32) J87.B33(33) J87.B34(34) J87.B35(35) J87.B37(37) J87.B38(38) J87.B39(39) J87.B40(40) J87.B42(42) J87.B43(43) J87.B44(44) J87.B45(45) J87.B47(47) J87.B48(48) J87.B49(49) J87.B50(50) J87.C1(1) J87.C3(3) J87.C5(5) J87.C7(7) J87.C9(9) J87.C10(10) J87.C12(12) J87.C13(13) J87.C14(14) J87.C15(15) J87.C17(17) J87.C18(18) J87.C19(19) J87.C20(20) J87.C22(22) J87.C23(23) J87.C24(24) J87.C25(25) J87.C27(27) J87.C28(28) J87.C29(29) J87.C30(30) J87.C32(32) J87.C33(33) J87.C34(34) J87.C35(35) J87.C37(37) J87.C38(38) J87.C39(39) J87.C40(40) J87.C42(42) J87.C43(43) J87.C44(44) J87.C45(45) J87.C47(47) J87.C48(48) J87.C49(49) J87.C50(50) J87.D2(2) J87.D4(4) J87.D6(6) J87.D8(8) J87.D10(10) J87.D11(11) J87.D12(12) J87.D13(13) J87.D14(14) J87.D15(15) J87.D16(16) J87.D17(17) J87.D18(18) J87.D19(19) J87.D20(20) J87.D21(21) J87.D22(22) J87.D23(23) J87.D24(24) J87.D25(25) J87.D26(26) J87.D27(27) J87.D28(28) J87.D29(29) J87.D30(30) J87.D31(31) J87.D32(32) J87.D33(33) J87.D34(34) J87.D35(35) J87.D36(36) J87.D37(37) J87.D38(38) J87.D39(39) J87.D40(40) J87.D41(41) J87.D42(42) J87.D43(43) J87.D44(44) J87.D45(45) J87.D46(46) J87.D47(47) J87.D48(48) J87.D49(49) J87.D50(50) J87.E1(1) J87.E3(3) J87.E5(5) J87.E7(7) J87.E9(9) J87.E10(10) J87.E11(11) J87.E12(12) J87.E13(13) J87.E14(14) J87.E15(15) J87.E16(16) J87.E17(17) J87.E18(18) J87.E19(19) J87.E20(20) J87.E21(21) J87.E22(22) J87.E23(23) J87.E24(24) J87.E25(25) J87.E26(26) J87.E27(27) J87.E28(28) J87.E29(29) J87.E30(30) J87.E31(31) J87.E32(32) J87.E33(33) J87.E34(34) J87.E35(35) J87.E36(36) J87.E37(37) J87.E38(38) J87.E39(39) J87.E40(40) J87.E41(41) J87.E42(42) J87.E43(43) J87.E44(44) J87.E45(45) J87.E46(46) J87.E47(47) J87.E48(48) J87.E49(49) J87.E50(50) J87.F2(2) J87.F4(4) J87.F6(6) J87.F8(8) J87.F10(10) J87.F11(11) J87.F12(12) J87.F13(13) J87.F15(15) J87.F16(16) J87.F17(17) J87.F18(18) J87.F20(20) J87.F21(21) J87.F22(22) J87.F23(23) J87.F25(25) J87.F26(26) J87.F27(27) J87.F28(28) J87.F30(30) J87.F31(31) J87.F32(32) J87.F33(33) J87.F35(35) J87.F36(36) J87.F37(37) J87.F38(38) J87.F40(40) J87.F41(41) J87.F42(42) J87.F43(43) J87.F45(45) J87.F46(46) J87.F47(47) J87.F48(48) J87.F50(50) J87.G1(1) J87.G3(3) J87.G5(5) J87.G7(7) J87.G9(9) J87.G10(10) J87.G11(11) J87.G12(12) J87.G13(13) J87.G15(15) J87.G16(16) J87.G17(17) J87.G18(18) J87.G20(20) J87.G21(21) J87.G22(22) J87.G23(23) J87.G25(25) J87.G26(26) J87.G27(27) J87.G28(28) J87.G30(30) J87.G31(31) J87.G32(32) J87.G33(33) J87.G35(35) J87.G36(36) J87.G37(37) J87.G38(38) J87.G40(40) J87.G41(41) J87.G42(42) J87.G43(43) J87.G45(45) J87.G46(46) J87.G47(47) J87.G48(48) J87.G50(50) J87.H2(2) J87.H4(4) J87.H6(6) J87.H8(8) J87.H10(10) J87.H11(11) J87.H12(12) J87.H13(13) J87.H14(14) J87.H15(15) J87.H16(16) J87.H17(17) J87.H18(18) J87.H19(19) J87.H20(20) J87.H21(21) J87.H22(22) J87.H23(23) J87.H24(24) J87.H25(25) J87.H26(26) J87.H27(27) J87.H28(28) J87.H29(29) J87.H30(30) J87.H31(31) J87.H32(32) J87.H33(33) J87.H34(34) J87.H35(35) J87.H36(36) J87.H37(37) J87.H38(38) J87.H39(39) J87.H40(40) J87.H41(41) J87.H42(42) J87.H43(43) J87.H44(44) J87.H45(45) J87.H46(46) J87.H47(47) J87.H48(48) J87.H49(49) J87.H50(50) J101.A1 J101.A2 J101.A3 J101.A4 J101.A5 J101.A6 J101.A7 J101.A8 J101.A9 J101.A10 J101.A11 J101.A12 J101.A13 J101.A14 J101.A15 J101.A16 J101.A17 J101.A18 J101.A19 J101.A20 J101.B1 J101.B4 J101.B7 J101.B10 J101.B11 J101.B14 J101.B17 J101.B20 J101.C1 J101.C2 J101.C3 J101.C4 J101.C5 J101.C6 J101.C7 J101.C8 J101.C9 J101.C10 J101.C11 J101.C12 J101.C13 J101.C14 J101.C15 J101.C16 J101.C17 J101.C18 J101.C19 J101.C20 J101.D1 J101.D2 J101.D3 J101.D4 J101.D7 J101.D8 J101.D9 J101.D10 J101.D11 J101.D14 J101.D15 J101.D16 J101.D17 J101.D18 J101.D19 J101.D20 J101.E1 J101.E4 J101.E7 J101.E10 J101.E11 J101.E14 J101.E17 J101.E20 J101.F1 J101.F2 J101.F3 J101.F4 J101.F5 J101.F6 J101.F7 J101.F8 J101.F9 J101.F10 J101.F11 J101.F12 J101.F13 J101.F14 J101.F15 J101.F16 J101.F17 J101.F18 J101.F19 J101.F20 J149.2(GND1) J149.3(GND2) J149.4(GND3) J149.5(GND4) J150.2(GND1) J150.3(GND2) J150.4(GND3) J150.5(GND4) MH1.1 MH2.1 MH3.1 MH4.1 MH5.1 MH6.1 R666.2 R667.2 R669.2 R670.2 R672.2 R673.2 R675.2 R701.2 R704.2 R705.2 R921.2 RFC5.1(GND) RFC5.2(GND) RFC5.3(GND) RFC6.1(GND) RFC6.2(GND) RFC6.3(GND) RFC7.1(GND) RFC7.2(GND) RFC7.3(GND) RFC8.1(GND) RFC8.2(GND) RFC8.3(GND) RFC10.1(GND) RFC10.2(GND) RFC10.3(GND) RFC12.1(GND) RFC12.2(GND) RFC12.3(GND) RFC15.1(GND) RFC15.2(GND) RFC15.3(GND) RFC16.1(GND) RFC16.2(GND) RFC16.3(GND) RFS15.1(GND) RFS15.2(GND) RFS15.3(GND) RFS15.4(GND) RFS15.5(GND) RFS16.1(GND) RFS16.2(GND) RFS16.3(GND) RFS16.4(GND) RFS16.5(GND) RFS17.1(GND) RFS17.2(GND) RFS17.3(GND) RFS17.4(GND) RFS17.5(GND) RFS18.1(GND) RFS18.2(GND) RFS18.3(GND) RFS18.4(GND) RFS18.5(GND) RFS19.1(GND) RFS19.2(GND) RFS19.3(GND) RFS19.4(GND) RFS19.5(GND) RFS20.1(GND) RFS20.2(GND) RFS20.3(GND) RFS20.4(GND) RFS20.5(GND) RFS21.1(GND) RFS21.2(GND) RFS21.3(GND) RFS21.4(GND) RFS21.5(GND) RFS22.1(GND) RFS22.2(GND) RFS22.3(GND) RFS22.4(GND) RFS22.5(GND) RFS23.1(GND) RFS23.2(GND) RFS23.3(GND) RFS23.4(GND) RFS23.5(GND) RFS24.1(GND) RFS24.2(GND) RFS24.3(GND) RFS24.4(GND) RFS24.5(GND) RFS25.1(GND) RFS25.2(GND) RFS25.3(GND) RFS25.4(GND) RFS25.5(GND) RFS26.1(GND) RFS26.2(GND) RFS26.3(GND) RFS26.4(GND) RFS26.5(GND) RFS27.1(GND) RFS27.2(GND) RFS27.3(GND) RFS27.4(GND) RFS27.5(GND) RFS28.1(GND) RFS28.2(GND) RFS28.3(GND) RFS28.4(GND) RFS28.5(GND) RFS29.1(GND) RFS29.2(GND) RFS29.3(GND) RFS29.4(GND) RFS29.5(GND) RFS30.1(GND) RFS30.2(GND) RFS30.3(GND) RFS30.4(GND) RFS30.5(GND) RFS31.1(GND) RFS31.2(GND) RFS31.3(GND) RFS31.4(GND) RFS31.5(GND) RFS37.1(GND) RFS37.2(GND) RFS37.3(GND) RFS37.4(GND) RFS37.5(GND) RFS38.1(GND) RFS38.2(GND) RFS38.3(GND) RFS38.4(GND) RFS38.5(GND) RFS39.1(GND) RFS39.2(GND) RFS39.3(GND) RFS39.4(GND) RFS39.5(GND) RFS40.1(GND) RFS40.2(GND) RFS40.3(GND) RFS40.4(GND) RFS40.5(GND) RFS41.1(GND) RFS41.2(GND) RFS41.3(GND) RFS41.4(GND) RFS41.5(GND) RFS42.1(GND) RFS42.2(GND) RFS42.3(GND) RFS42.4(GND) RFS42.5(GND) RFS45.1(GND) RFS45.2(GND) RFS45.3(GND) RFS45.4(GND) RFS45.5(GND) RFS46.1(GND) RFS46.2(GND) RFS46.3(GND) RFS46.4(GND) RFS46.5(GND) RFS49.1(GND) RFS49.2(GND) RFS49.3(GND) RFS49.4(GND) RFS49.5(GND) RFS50.1(GND) RFS50.2(GND) RFS50.3(GND) RFS50.4(GND) RFS50.5(GND) RFS56.1(GND) RFS56.2(GND) RFS56.3(GND) RFS56.4(GND) RFS56.5(GND) RFS57.1(GND) RFS57.2(GND) RFS57.3(GND) RFS57.4(GND) RFS57.5(GND) RFS58.1(GND) RFS58.2(GND) RFS58.3(GND) RFS58.4(GND) RFS58.5(GND) RFS59.1(GND) RFS59.2(GND) RFS59.3(GND) RFS59.4(GND) RFS59.5(GND) RFS60.1(GND) RFS60.2(GND) RFS60.3(GND) RFS60.4(GND) RFS60.5(GND) U96.A2(VSSQ1) U96.A8(VSSQ2) U96.A9(VSS9) U96.C8(VSS1) U96.D1(VSSQ3) U96.D9(VSSQ4) U96.E1(VSS2) U96.E9(VSS3) U96.G1(VSS4) U96.H9(VSS5) U96.K1(VSS6) U96.K9(VSS7) U96.N1(VSS8) U97.A2(VSSQ1) U97.A8(VSSQ2) U97.A9(VSS9) U97.C8(VSS1) U97.D1(VSSQ3) U97.D9(VSSQ4) U97.E1(VSS2) U97.E9(VSS3) U97.G1(VSS4) U97.H9(VSS5) U97.K1(VSS6) U97.K9(VSS7) U97.N1(VSS8) U98.A2(VSSQ1) U98.A8(VSSQ2) U98.A9(VSS9) U98.C8(VSS1) U98.D1(VSSQ3) U98.D9(VSSQ4) U98.E1(VSS2) U98.E9(VSS3) U98.G1(VSS4) U98.H9(VSS5) U98.K1(VSS6) U98.K9(VSS7) U98.N1(VSS8) U99.A2(VSSQ1) U99.A8(VSSQ2) U99.A9(VSS9) U99.C8(VSS1) U99.D1(VSSQ3) U99.D9(VSSQ4) U99.E1(VSS2) U99.E9(VSS3) U99.G1(VSS4) U99.H9(VSS5) U99.K1(VSS6) U99.K9(VSS7) U99.N1(VSS8) U128.1(1OE_B) U128.4(1DIR) U128.5(2DIR) U128.10(GND) U128.11(GND) U128.16(2OE_B) ; also on sheet 3 4 5 7 8 9 10 11 12 13 14 16 17 18 19 20 21 22 23 24 25 26 27 28 32 33 34 35 36 37 38 39 40 41 42 43 44 45 46 47 48 49 50 51 52 53 54 55 56 57 58 59 60 61 69 70 71 72
VCC1V2: C940.1 C942.1 C943.1 C944.1 C945.1 C946.1 C947.1 C948.1 C949.1 C950.1 C951.1 C954.1 C956.1 C957.1 C958.1 C959.1 C960.1 C961.1 C962.1 C963.1 C964.1 C965.1 C968.1 C970.1 C971.1 C972.1 C973.1 C974.1 C975.1 C976.1 C977.1 C978.1 C979.1 C982.1 C984.1 C993.1 C994.1 C995.1 C996.1 C997.1 C998.1 C999.1 C1000.1 C1001.1 C1002.1 R665.1 R668.1 R671.1 R674.1 R706.2 U96.A1(VDD1) U96.B2(VDDQ1) U96.B8(VDDQ2) U96.C1(VDDQ3) U96.C7(VDD2) U96.C9(VDDQ4) U96.E2(VDDQ5) U96.E8(VDDQ6) U96.F1(VDD3) U96.F9(VDD4) U96.H1(VDD5) U96.J9(VDD6) U96.M1(VDD7) U96.N9(VDD8) U97.A1(VDD1) U97.B2(VDDQ1) U97.B8(VDDQ2) U97.C1(VDDQ3) U97.C7(VDD2) U97.C9(VDDQ4) U97.E2(VDDQ5) U97.E8(VDDQ6) U97.F1(VDD3) U97.F9(VDD4) U97.H1(VDD5) U97.J9(VDD6) U97.M1(VDD7) U97.N9(VDD8) U98.A1(VDD1) U98.B2(VDDQ1) U98.B8(VDDQ2) U98.C1(VDDQ3) U98.C7(VDD2) U98.C9(VDDQ4) U98.E2(VDDQ5) U98.E8(VDDQ6) U98.F1(VDD3) U98.F9(VDD4) U98.H1(VDD5) U98.J9(VDD6) U98.M1(VDD7) U98.N9(VDD8) U99.A1(VDD1) U99.B2(VDDQ1) U99.B8(VDDQ2) U99.C1(VDDQ3) U99.C7(VDD2) U99.C9(VDDQ4) U99.E2(VDDQ5) U99.E8(VDDQ6) U99.F1(VDD3) U99.F9(VDD4) U99.H1(VDD5) U99.J9(VDD6) U99.M1(VDD7) U99.N9(VDD8) ; also on sheet 4 11 17 25 27 40 41 42 48 59
VCC1V8_BUS: C688.1 C689.1 C1503.1 J87.B1(1) J87.D1(1) U128.2(VCCB) ; also on sheet 4 9 10 12 20 21 22 23 24 25 26 27 34 36 37 38 39 42 52 61
VCC12_SW: C679.1 C680.1 C681.1 C690.1 C691.1 C692.1 J87.A6(6) J87.B7(7) J87.C6(6) J87.D7(7) J87.E6(6) J87.F7(7) J87.G6(6) J87.H7(7) ; also on sheet 28 31 43 44 45 47 48 49 50 51 52 57 58
CLK104_ADC_REFCLK_N: J101.B3
CLK104_ADC_REFCLK_P: J101.B2
CLK104_AMS_SYSREF_N: J101.B9 ; also on sheet 39
CLK104_AMS_SYSREF_P: J101.B8 ; also on sheet 39
CLK104_CLK_SPI_MUX_SEL0: J101.B5 U128.7(1A2)
CLK104_CLK_SPI_MUX_SEL0_LS: U128.14(1B2) ; also on sheet 5
CLK104_CLK_SPI_MUX_SEL1: J101.B6 U128.8(2A1)
CLK104_CLK_SPI_MUX_SEL1_LS: U128.13(2B1) ; also on sheet 5
CLK104_DAC_REFCLK_N: J101.E3 J150.1(SIG)
CLK104_DAC_REFCLK_P: J101.E2 J149.1(SIG)
CLK104_DDR_PLY_CAP_SYNC_N: J101.B19
CLK104_DDR_PLY_CAP_SYNC_P: J101.B18
CLK104_PL_CLK_N: J101.B16 ; also on sheet 5
CLK104_PL_CLK_P: J101.B15 ; also on sheet 5
CLK104_PL_SYSREF_N: J101.B13 ; also on sheet 39
CLK104_PL_SYSREF_P: J101.B12 ; also on sheet 39
CLK104_SCL: J101.E18 ; also on sheet 23
CLK104_SDA: J101.E19 ; also on sheet 23
CLK104_SFP_REC_CLK_N: J101.E16
CLK104_SFP_REC_CLK_P: J101.E15
CLK104_SYNC_IN: J101.E9
DAC227_T0_CH0_N: J87.F49(49) ; also on sheet 8
DAC227_T0_CH0_P: J87.G49(49) ; also on sheet 8
DAC227_T0_CH1_N: J87.F44(44) ; also on sheet 8
DAC227_T0_CH1_P: J87.G44(44) ; also on sheet 8
DAC227_T0_CH2_N: J87.F39(39) ; also on sheet 8
DAC227_T0_CH2_P: J87.G39(39) ; also on sheet 8
DAC227_T0_CH3_N: J87.F34(34) ; also on sheet 8
DAC227_T0_CH3_P: J87.G34(34) ; also on sheet 8
DAC228_T1_CH0_N: J87.F29(29) ; also on sheet 8
DAC228_T1_CH0_P: J87.G29(29) ; also on sheet 8
DAC228_T1_CH1_N: J87.F24(24) ; also on sheet 8
DAC228_T1_CH1_P: J87.G24(24) ; also on sheet 8
DAC228_T1_CH2_N: J87.F19(19) ; also on sheet 8
DAC228_T1_CH2_P: J87.G19(19) ; also on sheet 8
DAC228_T1_CH3_N: J87.F14(14) ; also on sheet 8
DAC228_T1_CH3_P: J87.G14(14) ; also on sheet 8
DAC_AVTT_BUS: C696.1 C697.1 J87.F1(1) ; also on sheet 55
DACIO_00: J87.A2(2) ; also on sheet 5
DACIO_01: J87.A4(4) ; also on sheet 5
DACIO_02: J87.B3(3) ; also on sheet 5
DACIO_03: J87.B5(5) ; also on sheet 5
DACIO_04: J87.C2(2) ; also on sheet 5
DACIO_05: J87.C4(4) ; also on sheet 5
DACIO_06: J87.D3(3) ; also on sheet 5
DACIO_07: J87.D5(5) ; also on sheet 5
DACIO_08: J87.E2(2) ; also on sheet 4
DACIO_09: J87.E4(4) ; also on sheet 4
DACIO_10: J87.F3(3) ; also on sheet 4
DACIO_11: J87.F5(5) ; also on sheet 4
DACIO_12: J87.G2(2) ; also on sheet 4
DACIO_13: J87.G4(4) ; also on sheet 4
DACIO_14: J87.H3(3) ; also on sheet 4
DACIO_15: J87.H5(5) ; also on sheet 4
PL_DDR4_C0_A0: R676.2 U96.L3(A0) U97.L3(A0) U98.L3(A0) U99.L3(A0) ; also on sheet 4
PL_DDR4_C0_A1: R677.2 U96.L7(A1) U97.L7(A1) U98.L7(A1) U99.L7(A1) ; also on sheet 4
PL_DDR4_C0_A2: R678.2 U96.M3(A2) U97.M3(A2) U98.M3(A2) U99.M3(A2) ; also on sheet 4
PL_DDR4_C0_A3: R679.2 U96.K3(A4) U97.K3(A4) U98.K7(A3) U99.K7(A3) ; also on sheet 4
PL_DDR4_C0_A4: R680.2 U96.K7(A3) U97.K7(A3) U98.K3(A4) U99.K3(A4) ; also on sheet 4
PL_DDR4_C0_A5: R681.2 U96.L2(A6) U97.L2(A6) U98.L8(A5) U99.L8(A5) ; also on sheet 4
PL_DDR4_C0_A6: R682.2 U96.L8(A5) U97.L8(A5) U98.L2(A6) U99.L2(A6) ; also on sheet 4
PL_DDR4_C0_A7: R683.2 U96.M2(A8) U97.M2(A8) U98.M8(A7) U99.M8(A7) ; also on sheet 4
PL_DDR4_C0_A8: R684.2 U96.M8(A7) U97.M8(A7) U98.M2(A8) U99.M2(A8) ; also on sheet 4
PL_DDR4_C0_A9: R685.2 U96.M7(A9) U97.M7(A9) U98.M7(A9) U99.M7(A9) ; also on sheet 4
PL_DDR4_C0_A10: R686.2 U96.J3(A10/AP) U97.J3(A10/AP) U98.J3(A10/AP) U99.J3(A10/AP) ; also on sheet 4
PL_DDR4_C0_A11: R687.2 U96.N8(A13) U97.N8(A13) U98.N2(A11) U99.N2(A11) ; also on sheet 4
PL_DDR4_C0_A12: R688.2 U96.J7(A12/BC_B) U97.J7(A12/BC_B) U98.J7(A12/BC_B) U99.J7(A12/BC_B) ; also on sheet 4
PL_DDR4_C0_A13: R689.2 U96.N2(A11) U97.N2(A11) U98.N8(A13) U99.N8(A13) ; also on sheet 4
PL_DDR4_C0_ACT_B: R697.2 U96.H3(ACT_B) U97.H3(ACT_B) U98.H3(ACT_B) U99.H3(ACT_B) ; also on sheet 4
PL_DDR4_C0_ALERT_B: R706.1 U96.L9(ALERT_B) U97.L9(ALERT_B) U98.L9(ALERT_B) U99.L9(ALERT_B) ; also on sheet 4
PL_DDR4_C0_BA0: R690.2 U96.K8(BA1) U97.K8(BA1) U98.K2(BA0) U99.K2(BA0) ; also on sheet 4
PL_DDR4_C0_BA1: R691.2 U96.K2(BA0) U97.K2(BA0) U98.K8(BA1) U99.K8(BA1) ; also on sheet 4
PL_DDR4_C0_BG0: R692.2 U96.J8(BG1) U97.J8(BG1) U98.J2(BG0) U99.J2(BG0) ; also on sheet 4
PL_DDR4_C0_BG1: R938.2 U96.J2(BG0) U97.J2(BG0) U98.J8(BG1) U99.J8(BG1) ; also on sheet 4
PL_DDR4_C0_CAS_B: R695.2 U96.H7(CAS_B) U97.H7(CAS_B) U98.H7(CAS_B) U99.H7(CAS_B) ; also on sheet 4
PL_DDR4_C0_CK0_C: R703.1 U96.F8(CK_C) U97.F8(CK_C) U98.F8(CK_C) U99.F8(CK_C) ; also on sheet 4
PL_DDR4_C0_CK0_T: R702.1 U96.F7(CK_T) U97.F7(CK_T) U98.F7(CK_T) U99.F7(CK_T) ; also on sheet 4
PL_DDR4_C0_CKE: R696.2 U96.G3(CKE) U97.G3(CKE) U98.G3(CKE) U99.G3(CKE) ; also on sheet 4
PL_DDR4_C0_CS1_B: R700.2 U98.G7(CS_B) U99.G7(CS_B) ; also on sheet 4
PL_DDR4_C0_CS2_B: R1108.2 U96.G7(CS_B) U97.G7(CS_B) ; also on sheet 4
PL_DDR4_C0_DM0_B: U96.A7(DM_TDQS_T) ; also on sheet 4
PL_DDR4_C0_DM1_B: U97.A7(DM_TDQS_T) ; also on sheet 4
PL_DDR4_C0_DM2_B: U98.A7(DM_TDQS_T) ; also on sheet 4
PL_DDR4_C0_DM3_B: U99.A7(DM_TDQS_T) ; also on sheet 4
PL_DDR4_C0_DQ0: U96.C2(DQ0) ; also on sheet 4
PL_DDR4_C0_DQ1: U96.B7(DQ1) ; also on sheet 4
PL_DDR4_C0_DQ2: U96.D3(DQ2) ; also on sheet 4
PL_DDR4_C0_DQ3: U96.D7(DQ3) ; also on sheet 4
PL_DDR4_C0_DQ4: U96.D2(DQ4/NC1) ; also on sheet 4
PL_DDR4_C0_DQ5: U96.D8(DQ5/NC2) ; also on sheet 4
PL_DDR4_C0_DQ6: U96.E3(DQ6/NC3) ; also on sheet 4
PL_DDR4_C0_DQ7: U96.E7(DQ7/NC4) ; also on sheet 4
PL_DDR4_C0_DQ8: U97.C2(DQ0) ; also on sheet 4
PL_DDR4_C0_DQ9: U97.B7(DQ1) ; also on sheet 4
PL_DDR4_C0_DQ10: U97.D3(DQ2) ; also on sheet 4
PL_DDR4_C0_DQ11: U97.D7(DQ3) ; also on sheet 4
PL_DDR4_C0_DQ12: U97.D2(DQ4/NC1) ; also on sheet 4
PL_DDR4_C0_DQ13: U97.D8(DQ5/NC2) ; also on sheet 4
PL_DDR4_C0_DQ14: U97.E3(DQ6/NC3) ; also on sheet 4
PL_DDR4_C0_DQ15: U97.E7(DQ7/NC4) ; also on sheet 4
PL_DDR4_C0_DQ16: U98.C2(DQ0) ; also on sheet 4
PL_DDR4_C0_DQ17: U98.B7(DQ1) ; also on sheet 4
PL_DDR4_C0_DQ18: U98.D3(DQ2) ; also on sheet 4
PL_DDR4_C0_DQ19: U98.D7(DQ3) ; also on sheet 4
PL_DDR4_C0_DQ20: U98.D2(DQ4/NC1) ; also on sheet 4
PL_DDR4_C0_DQ21: U98.D8(DQ5/NC2) ; also on sheet 4
PL_DDR4_C0_DQ22: U98.E3(DQ6/NC3) ; also on sheet 4
PL_DDR4_C0_DQ23: U98.E7(DQ7/NC4) ; also on sheet 4
PL_DDR4_C0_DQ24: U99.C2(DQ0) ; also on sheet 4
PL_DDR4_C0_DQ25: U99.B7(DQ1) ; also on sheet 4
PL_DDR4_C0_DQ26: U99.D3(DQ2) ; also on sheet 4
PL_DDR4_C0_DQ27: U99.D7(DQ3) ; also on sheet 4
PL_DDR4_C0_DQ28: U99.D2(DQ4/NC1) ; also on sheet 4
PL_DDR4_C0_DQ29: U99.D8(DQ5/NC2) ; also on sheet 4
PL_DDR4_C0_DQ30: U99.E3(DQ6/NC3) ; also on sheet 4
PL_DDR4_C0_DQ31: U99.E7(DQ7/NC4) ; also on sheet 4
PL_DDR4_C0_DQS0_C: U96.B3(DQS_C) ; also on sheet 4
PL_DDR4_C0_DQS0_T: U96.C3(DQS_T) ; also on sheet 4
PL_DDR4_C0_DQS1_C: U97.B3(DQS_C) ; also on sheet 4
PL_DDR4_C0_DQS1_T: U97.C3(DQS_T) ; also on sheet 4
PL_DDR4_C0_DQS2_C: U98.B3(DQS_C) ; also on sheet 4
PL_DDR4_C0_DQS2_T: U98.C3(DQS_T) ; also on sheet 4
PL_DDR4_C0_DQS3_C: U99.B3(DQS_C) ; also on sheet 4
PL_DDR4_C0_DQS3_T: U99.C3(DQS_T) ; also on sheet 4
PL_DDR4_C0_ODT: R699.2 U96.F3(ODT) U97.F3(ODT) U98.F3(ODT) U99.F3(ODT) ; also on sheet 4
PL_DDR4_C0_PARITY: R698.2 U96.N3(PAR) U97.N3(PAR) U98.N3(PAR) U99.N3(PAR) ; also on sheet 4
PL_DDR4_C0_RAS_B: R694.2 U96.H8(RAS_B) U97.H8(RAS_B) U98.H8(RAS_B) U99.H8(RAS_B) ; also on sheet 4
PL_DDR4_C0_REF_A: C941.1 R665.2 R666.1 U96.J1(VREFCA)
PL_DDR4_C0_REF_B: C955.1 R668.2 R669.1 U97.J1(VREFCA)
PL_DDR4_C0_REF_C: C969.1 R671.2 R672.1 U98.J1(VREFCA)
PL_DDR4_C0_REF_D: C983.1 R674.2 R675.1 U99.J1(VREFCA)
PL_DDR4_C0_RESET_B: R705.1 U96.L1(RESET_B) U97.L1(RESET_B) U98.L1(RESET_B) U99.L1(RESET_B) ; also on sheet 4
PL_DDR4_C0_TEN: R704.1 U96.G9(TEN_NC5) U97.G9(TEN_NC5) U98.G9(TEN_NC5) U99.G9(TEN_NC5)
PL_DDR4_C0_VTT: C985.1 C986.1 C987.1 C988.1 C989.1 C990.1 C991.1 C992.1 R676.1 R677.1 R678.1 R679.1 R680.1 R681.1 R682.1 R683.1 R684.1 R685.1 R686.1 R687.1 R688.1 R689.1 R690.1 R691.1 R692.1 R693.1 R694.1 R695.1 R696.1 R697.1 R698.1 R699.1 R700.1 R938.1 R1108.1 ; also on sheet 59
PL_DDR4_C0_WE_B: R693.2 U96.H2(WE_B) U97.H2(WE_B) U98.H2(WE_B) U99.H2(WE_B) ; also on sheet 4
PL_DDR4_C0_ZQA: R667.1 U96.B9(ZQ)
PL_DDR4_C0_ZQB: R670.1 U97.B9(ZQ)
PL_DDR4_C0_ZQC: R673.1 U98.B9(ZQ)
PL_DDR4_C0_ZQD: R701.1 U99.B9(ZQ)
UTIL_2V5: C952.1 C953.1 C966.1 C967.1 C980.1 C981.1 C1003.1 C1004.1 U96.B1(VPP1) U96.M9(VPP2) U97.B1(VPP1) U97.M9(VPP2) U98.B1(VPP1) U98.M9(VPP2) U99.B1(VPP1) U99.M9(VPP2) ; also on sheet 26 40 47 49
UTIL_3V3: C1131.1 C1132.1 C1133.1 C1502.1 J101.D5 J101.D6 J101.E5 J101.E6 U128.3(VCCA) ; also on sheet 9 10 20 22 23 24 25 26 27 28 29 30 31 33 34 36 37 40 42 43 44 45 47 49 51 53 54 55 56 57 59 60 61
UTIL_5V0: C1128.1 C1129.1 C1130.1 C1948.1 C1949.1 C1950.1 C1951.1 C1952.1 C1953.1 J87.A8(8) J87.B9(9) J87.C8(8) J87.D9(9) J87.E8(8) J87.F9(9) J87.G8(8) J87.H9(9) J101.D12 J101.D13 J101.E12 J101.E13 ; also on sheet 20 44 45 48 53 54 55 58 60 71 72
N23759317: C984.2 R702.2 R703.2
N24363036: R921.1 U128.12(2B2) U128.15(1B1)

Not connected (* = marked no-connect by the designer): J87 B11(11)* B16(16)* B21(21)* B26(26)* B31(31)* B36(36)* B41(41)* B46(46)* C11(11)* C16(16)* C21(21)* C26(26)* C31(31)* C36(36)* C41(41)* C46(46)* H1(1)*; J101 E8*; U96 A3(TDQS_C)* F2(C2_ODT1)* G2(C0_CKE1)* G8(C1_CS1_B)* N7(A17_NC6)*; U97 A3(TDQS_C)* F2(C2_ODT1)* G2(C0_CKE1)* G8(C1_CS1_B)* N7(A17_NC6)*; U98 A3(TDQS_C)* F2(C2_ODT1)* G2(C0_CKE1)* G8(C1_CS1_B)* N7(A17_NC6)*; U99 A3(TDQS_C)* F2(C2_ODT1)* G2(C0_CKE1)* G8(C1_CS1_B)* N7(A17_NC6)*; U128 6(1A1)* 9(2A2)*

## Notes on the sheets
sheet 63
- RFCAGE1 for U409
  MICRO & CORNER
- RFCAGE2 for U43
  MICRO & CORNER
sheet 65
- Layout: Place
  0.1UF cap in via
  matrix at M1
- PINS MIRRORED PER UG583
- BOTTOM
sheet 66
- Layout: Place
  0.1UF cap in via
  matrix at M1
- PINS MIRRORED PER UG583
- BOTTOM
sheet 67
- Layout: Place
  0.1UF cap in via
  matrix at M1
- TOP
sheet 68
- Layout: Place
  0.1UF cap in via
  matrix at M1
- TOP
